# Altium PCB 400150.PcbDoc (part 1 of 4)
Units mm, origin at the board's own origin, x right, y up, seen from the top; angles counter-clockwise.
Board outline 101.6 x 63.5 mm, 4 copper layers (Top Layer, Mid-Layer 1, Mid-Layer 2, Bottom Layer), stack 1.582 mm thick; 248 components, 179 nets, 1093 pads, 875 vias.
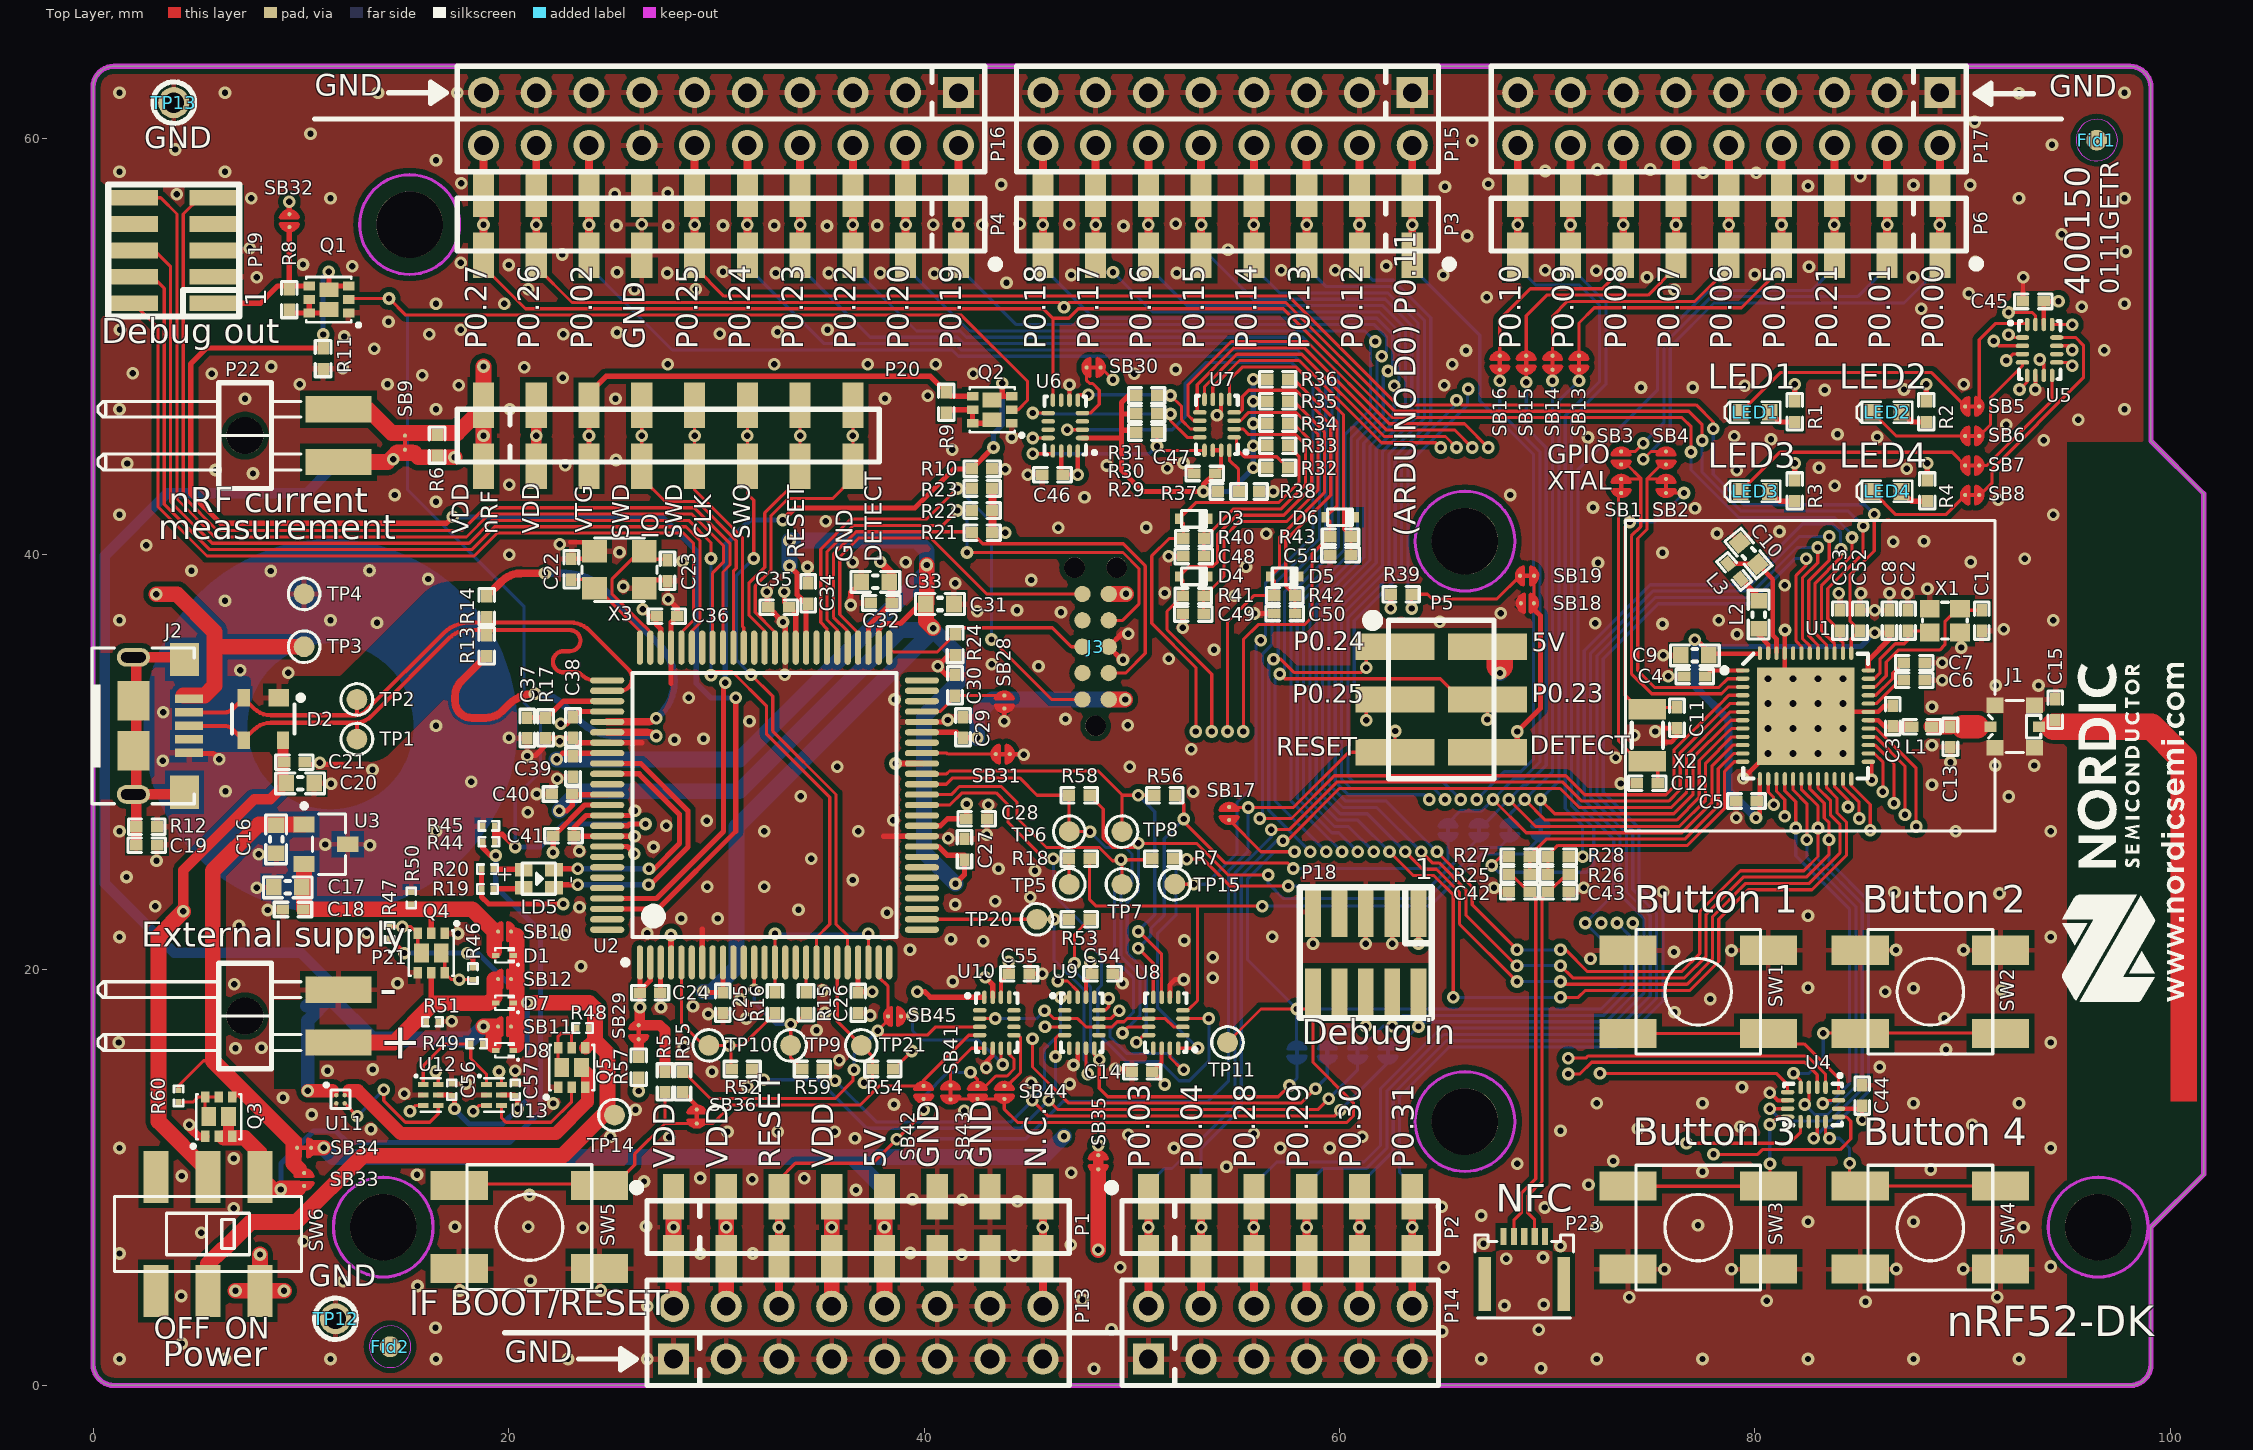
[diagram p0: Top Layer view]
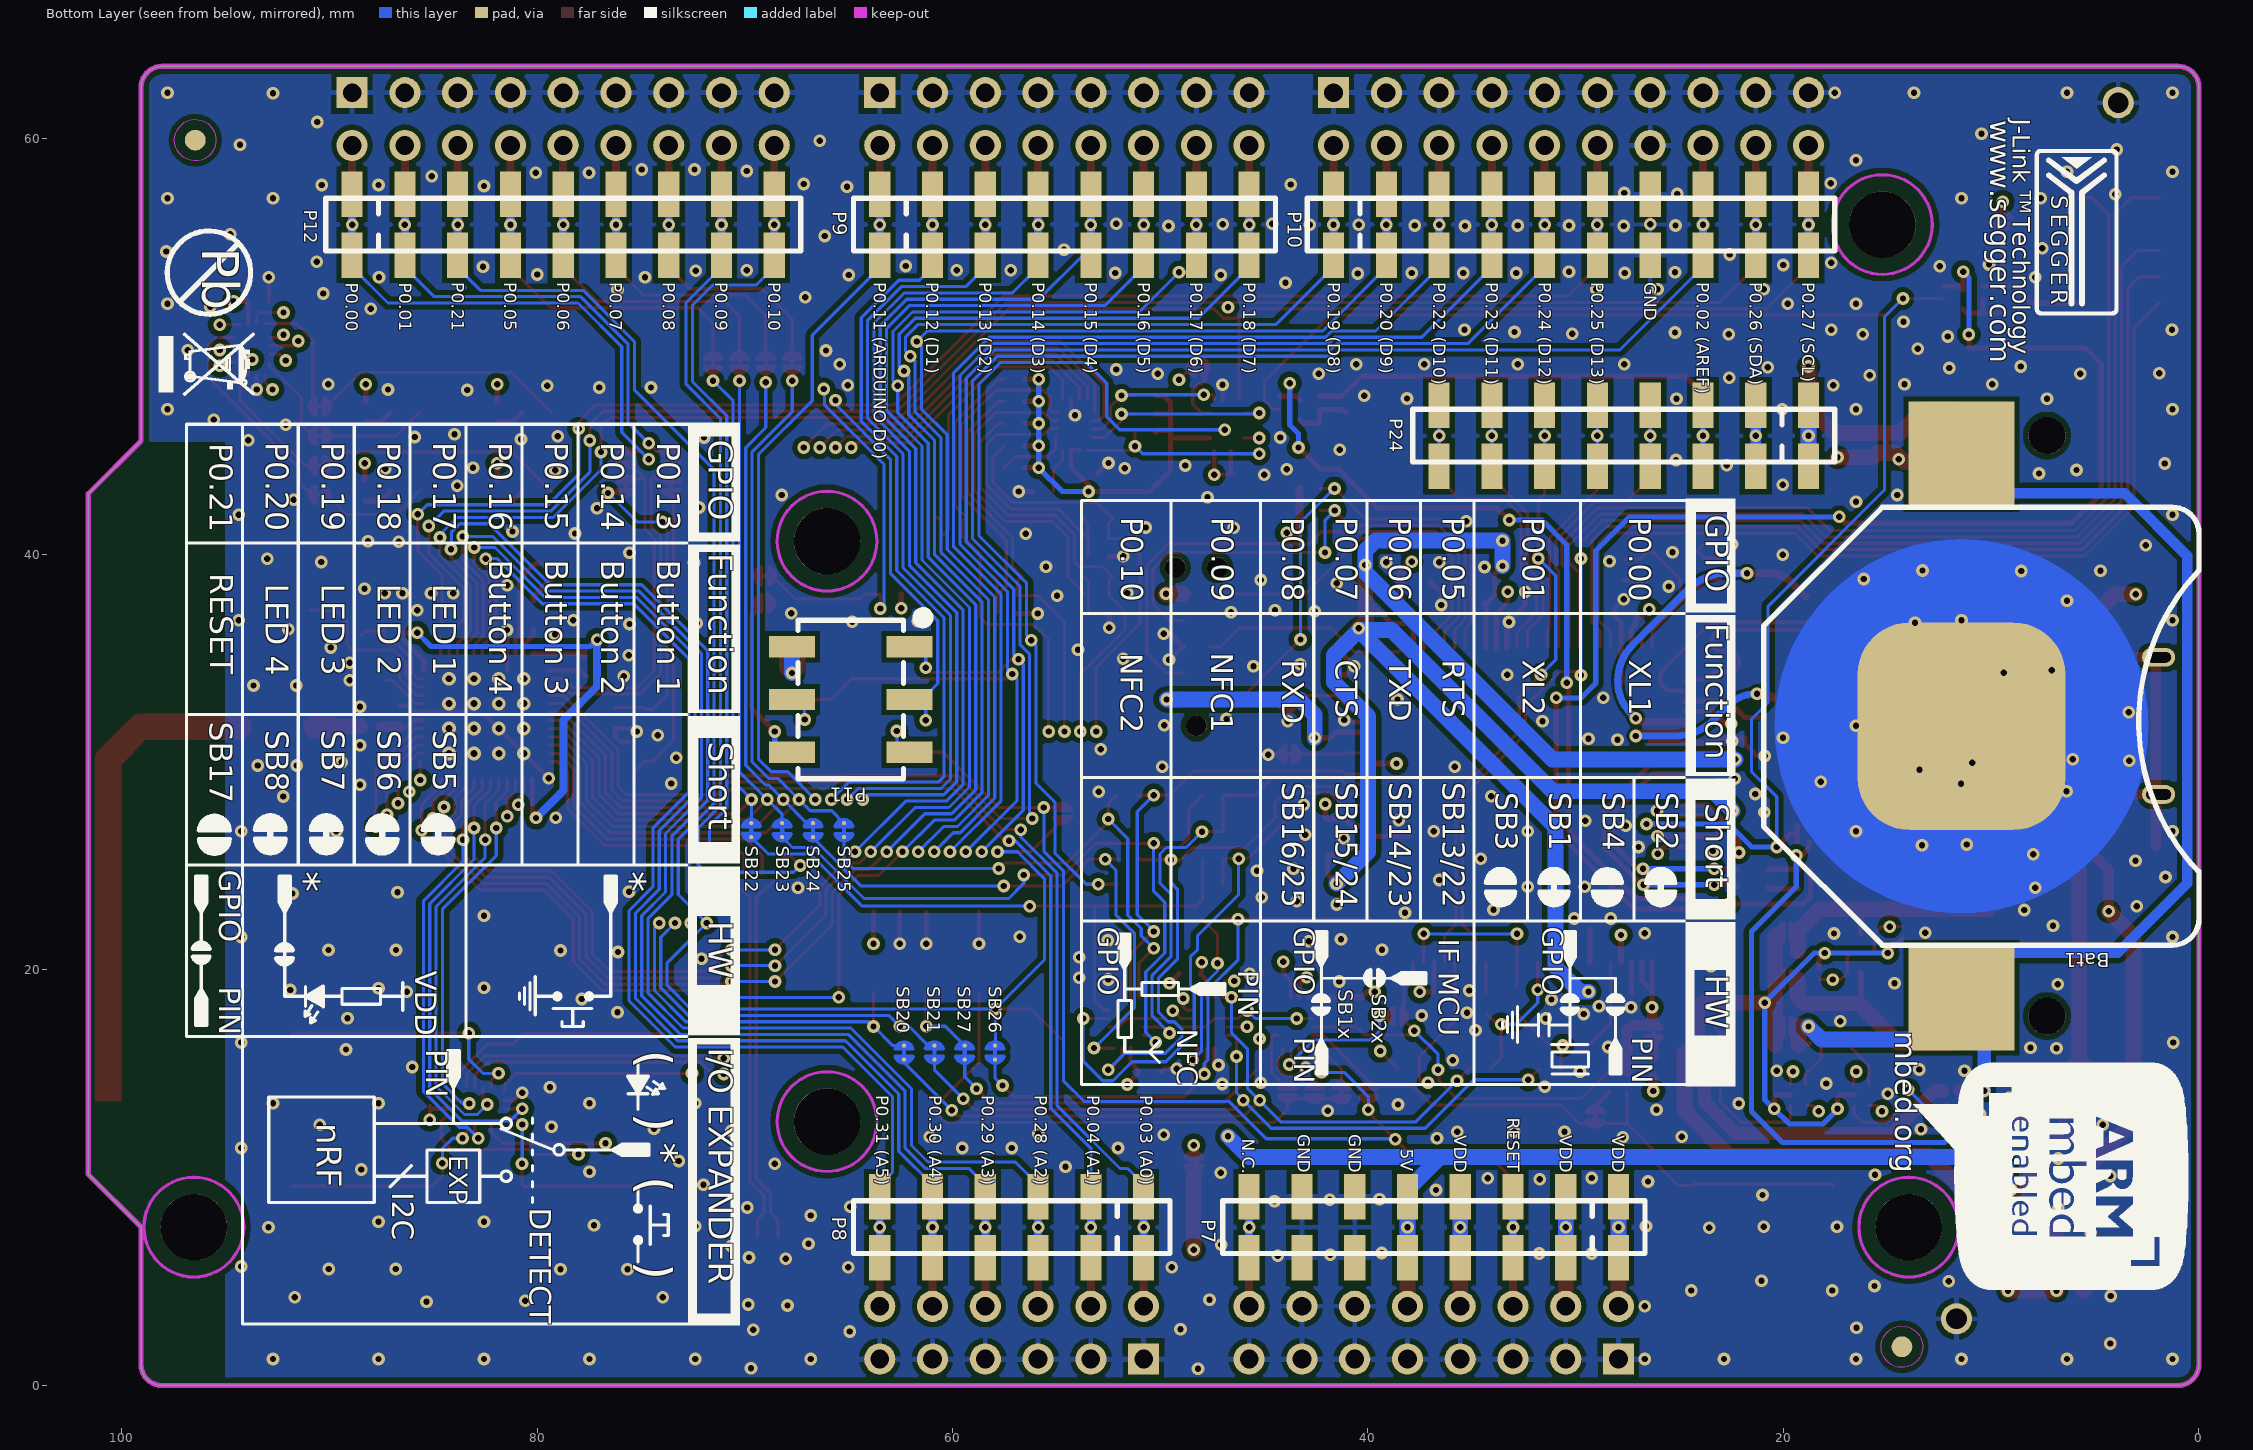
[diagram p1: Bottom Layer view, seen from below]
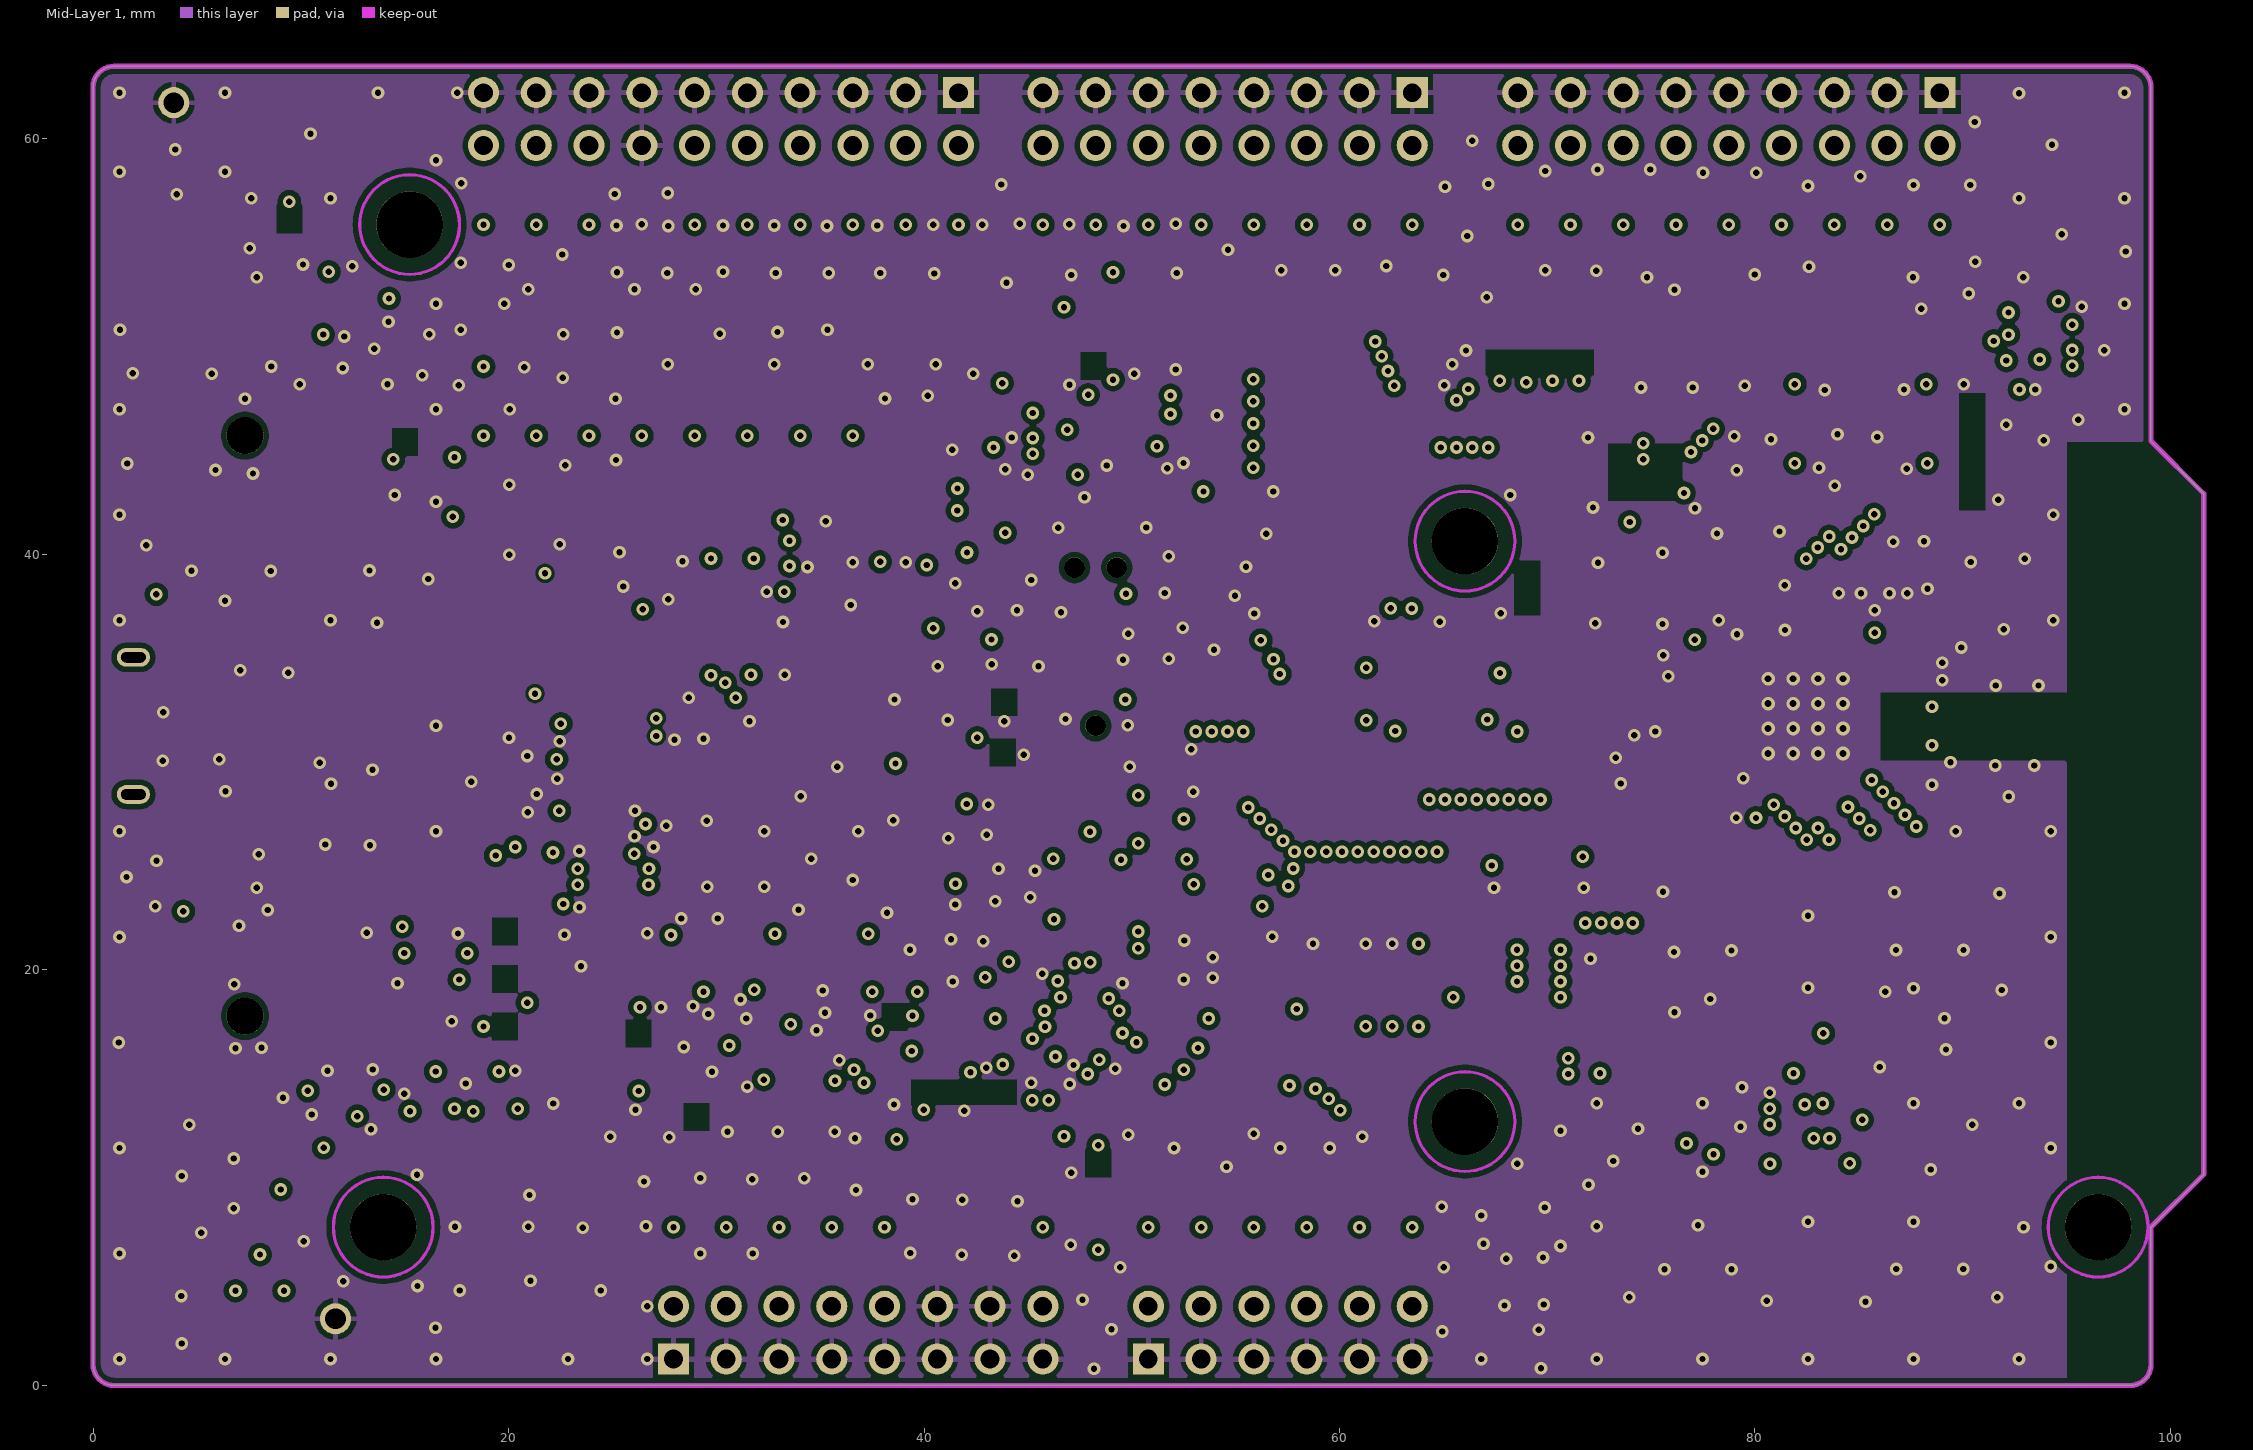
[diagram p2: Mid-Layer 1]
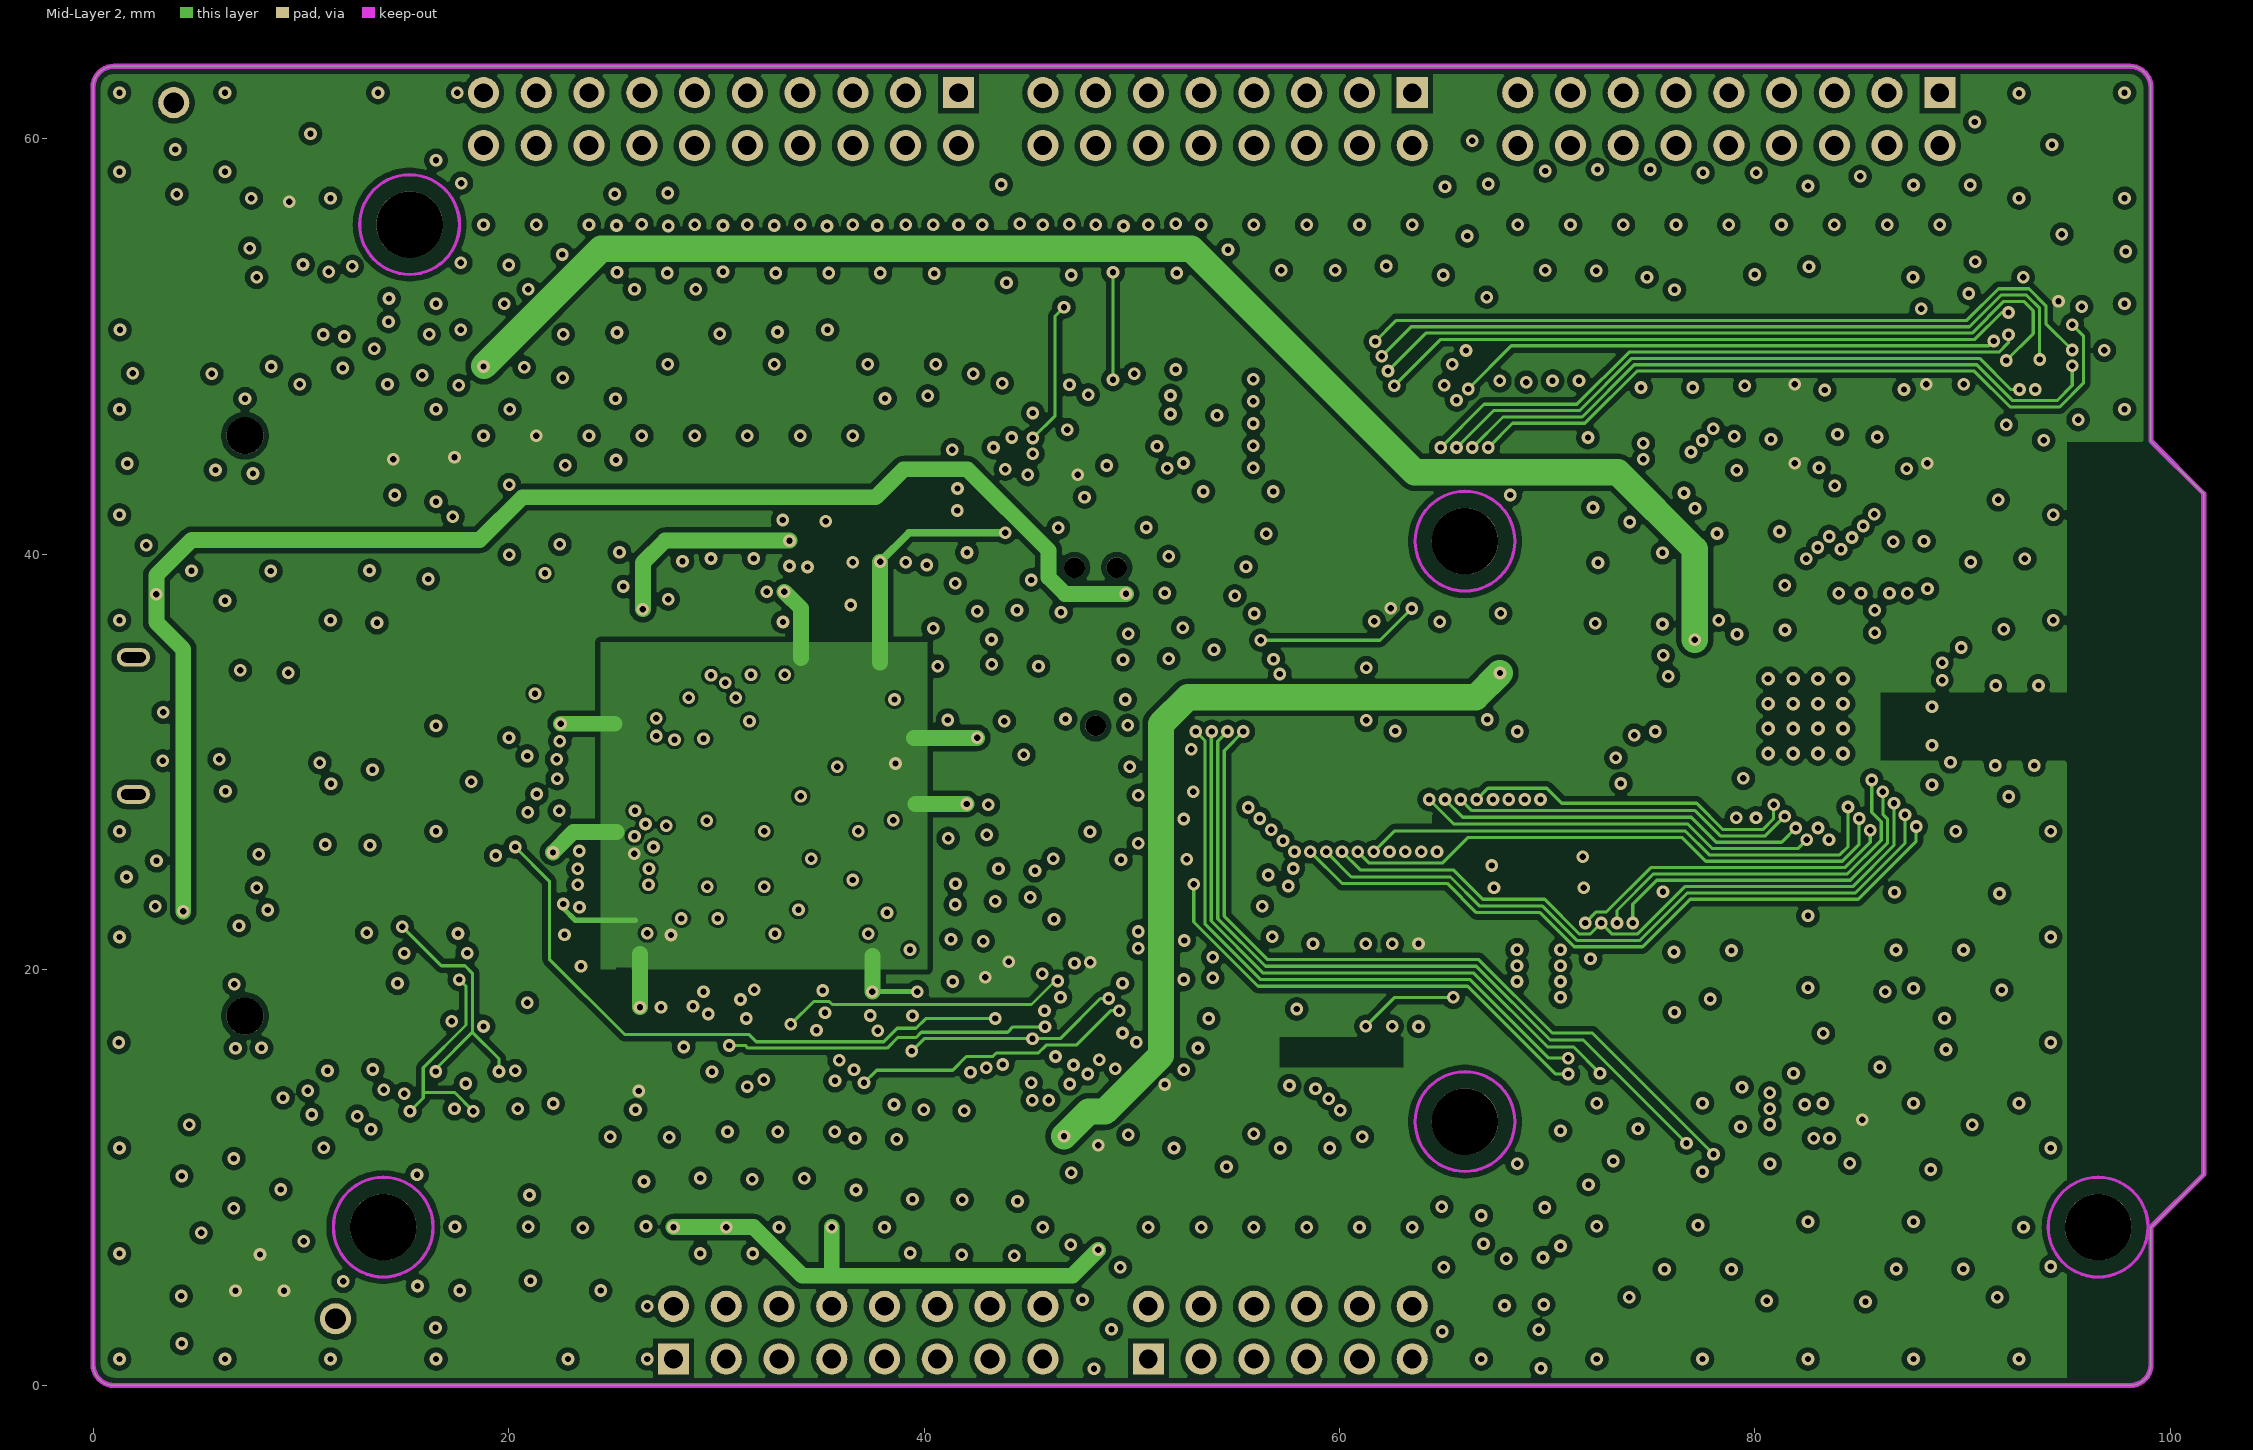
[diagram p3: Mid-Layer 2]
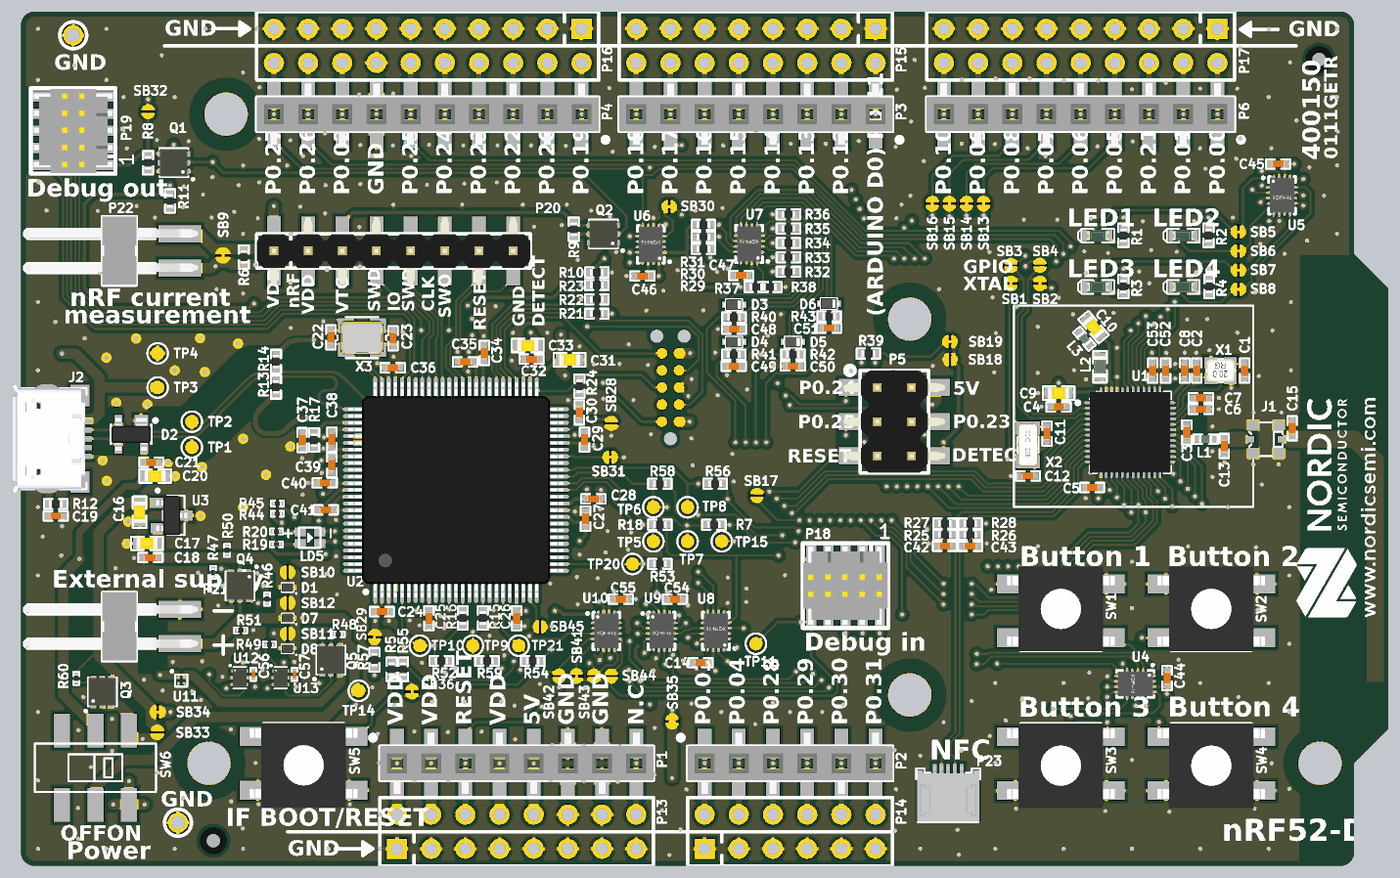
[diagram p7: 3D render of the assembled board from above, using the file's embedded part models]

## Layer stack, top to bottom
Top Solder: solder mask 0.0102, Solder Resist, Dk 3.5
Top Layer: signal copper 0.0356
Dielectric1: prepreg 0.18, FR-4, Dk 4.4
Mid-Layer 1: signal copper 0.0356
Dielectric2: core 1.08, FR-4, Dk 4.4
Mid-Layer 2: signal copper 0.0356
Dielectric3: prepreg 0.18, FR-4, Dk 4.4
Bottom Layer: signal copper 0.0356
Bottom Solder: solder mask 0.0102, Solder Resist, Dk 3.5

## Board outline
0,1.006 0,62.499 cw(c1.003,62.487) 1.016,63.49 98.044,63.49 cw(c98.044,62.474) 99.06,62.474 99.06,45.456 101.6,42.916 101.6,10.15 99.06,7.61 99.06,1.006 cw(c98.057,0.993) 98.069,-0.01 1.016,-0.01 cw(c1.016,1.006)

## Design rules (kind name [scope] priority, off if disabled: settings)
Clearance USB_Poly_Clearance [(InNamedPolygon('Top_Layer-GND')) vs (OnLayer('Mechanical 3'))] p1: gap=0.254 ignorepadtopadclearanceinfootprint=FALSE except(0: Arc-Hole Track-Hole SMDPad-Hole THPad-Hole Via-Hole Fill-Hole Poly-Hole Region-Hole Text-Hole)
Clearance USB_Clearance [(InDifferentialPairClass('All Differential Pairs'))] p2: gap=0.152 ignorepadtopadclearanceinfootprint=FALSE except(0: Arc-Hole Track-Hole SMDPad-Hole THPad-Hole Via-Hole Fill-Hole Poly-Hole Region-Hole Text-Hole)
Clearance ANT_Clerance [InNet('ANT') or InNet('RF')] p3: gap=0.203 ignorepadtopadclearanceinfootprint=FALSE except(0: Arc-Hole Track-Hole SMDPad-Hole THPad-Hole Via-Hole Fill-Hole Poly-Hole Region-Hole Text-Hole)
Clearance Polygon_Clearance [(InNamedPolygon('Top_Layer-GND')) or (InNamedPolygon('Bottom_Layer-GND')) or (InNamedPolygon('Mid_Layer_1-GND')) or (InNamedPolygon('Mid_Layer_2-VDD'))] p4: gap=0.254 ignorepadtopadclearanceinfootprint=FALSE except(0: Arc-Hole Track-Hole SMDPad-Hole THPad-Hole Via-Hole Fill-Hole Poly-Hole Region-Hole Text-Hole)
Clearance SB_Clearance [HasFootprint('Solderbridge') or HasFootprint('QFN40P180X140X55-10N')] p5: gap=0.127 ignorepadtopadclearanceinfootprint=FALSE except(0: Arc-Hole Track-Hole SMDPad-Hole THPad-Hole Via-Hole Fill-Hole Poly-Hole Region-Hole Text-Hole)
Clearance CSP_Clearance [HasFootprint('BGA4C40P2X2_76X76X62')] p6: gap=0.127 ignorepadtopadclearanceinfootprint=FALSE except(0: Arc-Hole Track-Hole SMDPad-Hole THPad-Hole Via-Hole Fill-Hole Poly-Hole Region-Hole Text-Hole)
Clearance P23_Clearance [HasFootprint('FPC_05P-0.5mm-RA-SMD')] p7: gap=0.127 ignorepadtopadclearanceinfootprint=FALSE except(0: Arc-Hole Track-Hole SMDPad-Hole THPad-Hole Via-Hole Fill-Hole Poly-Hole Region-Hole Text-Hole)
Clearance [All] p8: gap=0.152 ignorepadtopadclearanceinfootprint=FALSE except(0: Arc-Hole Track-Hole SMDPad-Hole THPad-Hole Via-Hole Fill-Hole Poly-Hole Region-Hole Text-Hole)
ComponentClearance [All] p1 off: gap=0.254 collisioncheckmode=3 verticalgap=0.254 showdistances=FALSE
DiffPairsRouting [All] p1: maxlimit=0.254 minlimit=0.15 mostfreqgap=0.254 toplayer_maxgap=0.15 toplayer_prefgap=0.15 toplayer_minwidth=0.203 toplayer_maxwidth=0.381 toplayer_prefwidth=0.381 midlayer1_mingap=0.254 midlayer1_minwidth=0.203 midlayer1_maxwidth=0.381 midlayer1_prefwidth=0.381 midlayer2_mingap=0.254 midlayer2_minwidth=0.203 midlayer2_maxwidth=0.381 midlayer2_prefwidth=0.381 bottomlayer_maxgap=0.15 bottomlayer_prefgap=0.15 bottomlayer_minwidth=0.203 bottomlayer_maxwidth=0.381 bottomlayer_prefwidth=0.381 maxuncoupledlength=12.7
FabricationTestPointUsage TestPointUsage [All] p1: valid=0 allowmultiple=FALSE
FabricationTestpoint Testpoint [All] p1: side=3 testpointundercomponent=TRUE minsize=1.016 maxsize=2.54 preferedsize=1.524 minholesize=0 maxholesize=1.016 preferedholesize=0.813 testpointgrid=0.025 allowsidetop=TRUE allowsidebottom=TRUE usegrid=TRUE gridtolerance=0
Height [All] p1 off: minheight=0 maxheight=25.4 prefheight=12.7
HoleSize [All] p1: absolutevalues=TRUE maxlimit=5 minlimit=0.305 maxpercent=80.000 minpercent=20.000
HoleToHoleClearance HoleToHoleClearance_L1L2 [InDrillLayerPair('Top Layer - Mid-Layer 1') vs InDrillLayerPair('Top Layer - Mid-Layer 1')] p1: gap=0.225 allowstackedmicrovias=TRUE
HoleToHoleClearance HoleToHoleClearance_L1L2_L1L3 [InDrillLayerPair('Top Layer - Mid-Layer 1') vs InDrillLayerPair('Top Layer - Mid-Layer 2')] p2: gap=0.225 allowstackedmicrovias=TRUE
HoleToHoleClearance HoleToHoleClearance_L1L3 [InDrillLayerPair('Top Layer - Mid-Layer 2') vs InDrillLayerPair('Top Layer - Mid-Layer 2')] p3: gap=0.225 allowstackedmicrovias=TRUE
HoleToHoleClearance HoleToHoleClearance_L1L3_L3L4 [InDrillLayerPair('Top Layer - Mid-Layer 2') vs InDrillLayerPair('Mid-Layer 2 - Mid-Layer 3')] p4: gap=0.225 allowstackedmicrovias=TRUE
HoleToHoleClearance HoleToHoleClearance_L3L4 [InDrillLayerPair('Mid-Layer 2 - Mid-Layer 3') vs InDrillLayerPair('Mid-Layer 2 - Mid-Layer 3')] p5: gap=0.225 allowstackedmicrovias=TRUE
HoleToHoleClearance HoleToHoleClearance_L3L4_L4L6 [InDrillLayerPair('Mid-Layer 2 - Mid-Layer 3') vs InDrillLayerPair('Mid-Layer 3 - Bottom Layer')] p6: gap=0.225 allowstackedmicrovias=TRUE
HoleToHoleClearance HoleToHoleClearance_L4L6 [InDrillLayerPair('Mid-Layer 3 - Bottom Layer') vs InDrillLayerPair('Mid-Layer 3 - Bottom Layer')] p7: gap=0.225 allowstackedmicrovias=TRUE
HoleToHoleClearance HoleToHoleClearance_L1L2_L1L6 [InDrillLayerPair('Top Layer - Mid-Layer 1') vs InDrillLayerPair('Top Layer - Bottom Layer')] p8: gap=0.275 allowstackedmicrovias=FALSE
HoleToHoleClearance HoleToHoleClearance_L1L3_L1L6 [InDrillLayerPair('Top Layer - Mid-Layer 2') vs InDrillLayerPair('Top Layer - Bottom Layer')] p9: gap=0.275 allowstackedmicrovias=FALSE
HoleToHoleClearance HoleToHoleClearance_L3L4_L1L6 [InDrillLayerPair('Mid-Layer 2 - Mid-Layer 3') vs InDrillLayerPair('Top Layer - Bottom Layer')] p10: gap=0.275 allowstackedmicrovias=FALSE
HoleToHoleClearance HoleToHoleClearance_L4L6_L1L6 [InDrillLayerPair('Mid-Layer 3 - Bottom Layer') vs InDrillLayerPair('Top Layer - Bottom Layer')] p11: gap=0.275 allowstackedmicrovias=FALSE
HoleToHoleClearance HoleToHoleClearance_L1L6 [InDrillLayerPair('Top Layer - Bottom Layer') vs InDrillLayerPair('Top Layer - Bottom Layer')] p12: gap=0.45 allowstackedmicrovias=FALSE
HoleToHoleClearance [All] p13: gap=0.254 allowstackedmicrovias=TRUE
MinimumAnnularRing [All] p1 off: minimumring=0.152
MinimumSolderMaskSliver MinimumSolderMaskSliver_U11 [InComponent('U11')] p1: minsoldermaskwidth=0.08
MinimumSolderMaskSliver [All] p2: minsoldermaskwidth=0.097
PolygonConnect PolygonConnect_1 [isVia and innet(gnd) or isVia and innet('VDD') or HasFootprint('COAXIAL-SWF') or isVia and innet('VDD_SAM')] p1: connectstyle=Direct reliefconductorwidth=0.254 reliefentries=4 polygonreliefangle="90 Angle" airgapwidth=0.254
PolygonConnect [All] p2: connectstyle=Relief reliefconductorwidth=0.254 reliefentries=4 polygonreliefangle="90 Angle" airgapwidth=0.254
RoutingVias [All] p1: holewidth=0.305 width=0.61 viastyle="Through Hole" minholewidth=0.305 minwidth=0.61 maxholewidth=0.711 maxwidth=1.27
SilkToSolderMaskClearance SilkscreenOverComponentPads [IsPad] p1: minsilkscreentomaskgap=0.254 clearancetoexposedcopper=TRUE
SolderMaskExpansion [All] p1: expansion=0.076
Width [All] p1: maxlimit=10.16 minlimit=0.152 preferedwidth=0.152 minimp=50.000000 maximp=50.000000 favimp=50.000000
21 further rules are at their usual default settings.

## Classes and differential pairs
component class sheet1_cover: Fid1 Fid2
component class sheet2_radio: C1 C2 C3 C4 C5 C6 C7 C8 C9 C10 C11 C12 C13 C15 C52 C53 J1 L1 L2 L3 SB1 SB2 SB3 SB4 U1 X1 X2
component class sheet3_pin_map: SB13 SB14 SB15 SB16 SB17 SB30 TP11
component class sheet4_interface_mcu: C14 C22 C23 C24 C25 C26 C27 C28 C29 C30 C31 C32 C33 C34 C35 C36 C37 C38 C39 C40 C41 C54 C55 LD5 Q1 Q2 R7 R8 R9 R10 R11 R15 R16 R17 R18 R19 R20 R52 R53 R54 R55 R56 R57 R58 R59 SB20 SB21 SB22 SB23 SB24 SB25 SB26 SB27 SB28 SB29 SB31 SB36 SB41 SB42 SB43 SB44 SB45 SB? TP5 TP6 TP7 TP8 TP9 TP10 TP20 TP21 U2 U8 U9 U10 X3
component class sheet5_buttons_and_leds: C44 C45 C46 C47 C48 C49 C50 C51 D3 D4 D5 D6 LED1 LED2 LED3 LED4 R1 R2 R3 R4 R5 R29 R30 R31 R32 R33 R34 R35 R36 R37 R38 R40 R41 R42 R43 SB5 SB6 SB7 SB8 SW1 SW2 SW3 SW4 SW5 U4 U5 U6 U7
component class sheet6_connectors: C19 C20 C21 C42 C43 D2 J2 J3 P1 P2 P3 P4 P5 P6 P7 P8 P9 P10 P11 P12 P13 P14 P15 P16 P17 P18 P19 P20 P23 P24 R12 R13 R14 R21 R22 R23 R24 R25 R26 R27 R28 R39 SB18 SB19 SB32 TP1 TP2 TP3 TP4 TP15
component class sheet7_power_supply: Bat1 C16 C17 C18 C56 C57 D1 D7 D8 P21 P22 Q3 Q4 Q5 R6 R44 R45 R46 R47 R48 R49 R50 R51 R60 SB9 SB10 SB11 SB12 SB33 SB34 SB35 SW6 TP12 TP13 TP14 U3 U11 U12 U13
differential pair DHSD: +DHSD_P -DHSD_N
differential pair DFSD: +DFSD_P -DFSD_N

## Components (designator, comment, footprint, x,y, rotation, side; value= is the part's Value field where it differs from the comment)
Bat1 "Bat Holder CR2032" CR2032_HOLDER_SMD 11.43,31.725 r270 bottom locked
C1 "12pF" CAPC1005X04L 90.918,36.809 r270 top
C2 "12pF" CAPC1005X04L 87.362,36.809 r90 top
C3 "0.8pF" CAPC1005X04L 86.626,32.211 r270 top
C4 "100nF" CAPC1005X04L 77.101,34.116 r180 top
C5 "100nF" CAPC1005X04L 79.59,28.122 r180 top
C6 "N.C." CAPC1005X04L 87.667,33.938 r0 top
C7 "100pF" CAPC1005X04L 87.667,34.777 r0 top
C8 "100nF" CAPC1005X04L 86.473,36.809 r90 top
C9 "4.7µF" CAPC1608X06L 77.101,35.132 r180 top
C10 "1.0µF" CAPC1608X06L 79.692,40.04 r310 top
C11 "12pF" CAPC1005X04L 76.241,32.127 r90 top
C12 "12pF" CAPC1005X04L 74.819,28.977 r0 top
C13 "N.C." CAPC1005X04L 89.408,31.206 r270 top
C14 "100nF" CAPC1005X04L 50.495,15.088 r0 top
C15 "1.2pF" CAPC1005X04L 94.459,32.516 r90 top
C16 "1.0µF" CAPC1608X06L 8.814,26.279 r90 top
C17 "1.0µF" CAPC1608X06L 9.373,23.967 r0 top
C18 "100nF" CAPC1005X04L 9.627,22.901 r0 top
C19 "100nF" CAPC1005X04L 2.587,25.999 r180 top
C20 "10µF" CAPC1608X06L 9.972,28.971 r180 top
C21 "100nF" CAPC1005X04L 9.693,29.987 r180 top
C22 "18pF" CAPC1005X04L 23.028,39.284 r90 top
C23 "18pF" CAPC1005X04L 27.651,39.207 r270 top
C24 "100nF" CAPC1005X04L 26.812,18.887 r180 top
C25 "100nF" CAPC1005X04L 30.318,18.405 r90 top
C26 "100nF" CAPC1005X04L 36.83,18.405 r90 top
C27 "100nF" CAPC1005X04L 41.951,25.796 r270 top
C28 "100nF" CAPC1005X04L 42.535,27.269 r180 top
C29 "100nF" CAPC1005X04L 41.875,31.664 r270 top
C30 "10nF" CAPC1005X04L 41.494,33.696 r270 top
C31 "10µF" CAPC1608X06L 40.767,37.607 r180 top
C32 "100nF" CAPC1005X04L 37.938,37.658 r0 top
C33 "10µF" CAPC1608X06L 37.658,38.674 r0 top
C34 "100nF" CAPC1005X04L 34.432,38.115 r270 top
C35 "100nF" CAPC1005X04L 33.01,37.455 r0 top
C36 "100nF" CAPC1005X04L 27.625,37.023 r0 top
C37 "10pF" CAPC1005X04L 20.894,31.638 r90 top
C38 "100nF" CAPC1005X04L 23.104,31.664 r90 top
C39 "100nF" CAPC1005X04L 23.104,29.784 r90 top
C40 "100nF" CAPC1005X04L 22.571,28.463 r0 top
C41 "100nF" CAPC1005X04L 22.647,26.457 r180 top
C42 "300pF" CAPC1005X04L 68.656,23.749 r180 top
C43 "300pF" CAPC1005X04L 70.536,23.749 r180 top
C44 "100nF" CAPC1005X04L 85.158,13.945 r270 top
C45 "100nF" CAPC1005X04L 93.396,52.172 r0 top
C46 "100nF" CAPC1005X04L 46.185,43.835 r0 top
C47 "100nF" CAPC1005X04L 53.518,43.885 r0 top
C48 "1.0µF" CAPC1005X04L 52.984,39.898 r180 top
C49 "1.0µF" CAPC1005X04L 52.961,37.129 r0 top
C50 "1.0µF" CAPC1005X04L 57.361,37.147 r0 top
C51 "1.0µF" CAPC1005X04L 60.048,39.972 r180 top
C52 "12pF" CAPC1005X04L 85.051,36.809 r90 top
C53 "12pF" CAPC1005X04L 84.086,36.809 r90 top
C54 "100nF" CAPC1005X04L 48.59,19.812 r180 top
C55 "100nF" CAPC1005X04L 44.577,19.812 r180 top
C56 "100nF" CAPC0603X03L_C 17.272,14.224 r270 top
C57 "100nF" CAPC0603X03L_C 20.32,14.224 r270 top
D1 "NSR0620P2T5G" SODFL100X40-2N 19.812,20.691 r180 top
D2 "PRTR5V0U2X" SOT190P230X110-4L 8.194,32.07 r270 top
D3 "1PS79SB30.115" SOD-523 52.99,41.701 r180 top
D4 "1PS79SB30.115" SOD-523 52.992,38.932 r180 top
D5 "1PS79SB30.115" SOD-523 57.361,38.932 r180 top
D6 "1PS79SB30.115" SOD-523 60.028,41.783 r180 top
D7 "NSR0620P2T5G" SODFL100X40-2N 19.812,18.405 r180 top
D8 "NSR0620P2T5G" SODFL100X40-2N 19.812,16.119 r180 top
Fid1 "Fiducial mark" Fiducial 96.451,59.934 r180 top
Fid2 "Fiducial mark" Fiducial 14.3,1.854 r0 top
J1 "MM8130-2600" COAXIAL-SWF 92.504,31.703 r90 top
J2 "MicroUSB-B" USB-Micro-B-RA-SMD-PiP 4.619,31.74 r0 top
J3 "TC2050-IDC" TC2050-IDC-NLFP 48.26,35.55 r90 top locked
L1 "3.9nH" INDC1005X04L 88.023,31.703 r0 top
L2 "10µH" INDC1608X06L 80.174,37.093 r270 top
L3 "15nH" INDC1005X04L 79.007,39.176 r310 top
LD5 "LED RG" LED_DUAL_0606 21.463,24.384 r90 top
LED1 "L0603G" LED_0603_G 80.01,46.837 r0 top
LED2 "L0603G" LED_0603_G 86.36,46.837 r0 top
LED3 "L0603G" LED_0603_G 80.01,43.027 r0 top
LED4 "L0603G" LED_0603_G 86.36,43.027 r0 top
P1 "Socket 1x8" SOCKET_1x8_SMD 27.94,7.61 r0 top locked
P2 "Socket 1x6" SOCKET_1x6_SMD 50.8,7.61 r0 top locked
P3 "Socket 1x8" SOCKET_1x8_SMD 63.5,55.87 r180 top locked
P4 "Socket 1x10" SOCKET_1x10_SMD 41.656,55.87 r180 top locked
P5 "Pin Hdr 2x3" HDR_2x3-SMD 64.897,33.01 r270 top locked
P6 "Socket 1x9" SOCKET_1x9_SMD 88.9,55.87 r180 top locked
P7 "Pin List 1x8" LIST_1x8_SMD-NC 27.94,7.61 r0 bottom
P8 "Pin List 1x6" LIST_1x6_SMD-NC 50.8,7.61 r0 bottom locked
P9 "Pin List 1x8" LIST_1x8_SMD-NC 63.5,55.87 r180 bottom locked
P10 "Pin List 1x10" LIST_1x10_SMD-NC 41.656,55.87 r180 bottom locked
P11 "Socket 2x3" SOCKET_2x3_SMD-2.54mm-bottom-NC 64.897,33.01 r270 top locked
P12 "Pin List 1x9" LIST_1x9_SMD-NC 88.9,55.87 r180 bottom locked
P13 "Pin Header 2x8" HDR_2x8-NC 36.83,2.53 r0 top locked
P14 "Pin Header 2x6" HDR_2x6-NC 57.15,2.53 r0 top locked
P15 "Pin Header 2x8" HDR_2x8-NC 54.61,60.95 r180 top locked
P16 "Pin Header 2x10" HDR_2x10-NC 30.226,60.95 r180 top locked
P17 "Pin Header 2x9" HDR_2x9-NC 78.74,60.95 r180 top
P18 "Pin Header 2x5, 1.27mm" HDR_2x5-SMD-1.27mm-K 61.265,20.822 r180 top
P19 "Pin Header 2x5, 1.27mm" HDR_2x5-SMD-1.27mm-K 3.886,54.625 r90 top locked
P20 "Pin List 1x8" LIST_1x8_SMD 18.796,45.71 r0 top
P21 "Pin List 1x2, Angled" LIST_ANG_1x2-SMD-2.54MM 11.811,17.77 r270 top
P22 "Pin List 1x2, Angled" LIST_ANG_1x2-SMD-2.54MM 11.811,45.71 r270 top
P23 "FPC 0.5mm RA SMD" FPC_05P-0.5mm-RA-SMD 67.894,7.163 r0 top
P24 "Socket 1x8" LIST_1x8_SMD-NC 18.796,45.71 r0 bottom
Q1 "TSM2537CQ RFG" DFN65P200X200X80_HS-6N 11.354,52.263 r180 top
Q2 "TSM2537CQ RFG" DFN65P200X200X80_HS-6N 43.282,46.954 r180 top
Q3 "TSM2537CQ RFG" DFN65P200X200X80_HS-6N 6.045,12.929 r90 top
Q4 "TSM250N02DCQ RFG" DFN65P200X200X80_HS-6N 16.281,20.803 r270 top
Q5 "TSM2537CQ RFG" DFN65P200X200X80_HS-6N 23.038,15.291 r90 top
R1 "220R" RESC1005X04L 81.915,46.863 r90 top
R2 "220R" RESC1005X04L 88.24,46.863 r90 top
R3 "220R" RESC1005X04L 81.915,43.053 r90 top
R4 "220R" RESC1005X04L 88.291,43.053 r90 top
R5 "10k" RESC1005X04L 27.532,14.601 r90 top
R6 "N.C." RESC1005X04L 16.561,45.253 r90 top
R7 "0R" RESC1005X04L 51.486,25.349 r180 top
R8 "10k" RESC1005X04L 9.449,52.263 r270 top
R9 "10k" RESC1005X04L 41.072,47.31 r270 top
R10 "10k" RESC1005X04L 42.795,44.11 r180 top
R11 "10k" RESC1005X04L 11.074,49.418 r90 top
R12 "10k" RESC1005X04L 2.587,26.888 r180 top
R13 "39R" RESC1005X04L 18.949,35.593 r90 top
R14 "39R" RESC1005X04L 18.949,37.479 r270 top
R15 "150R" RESC1005X04L 34.324,18.415 r270 top
R16 "150R" RESC1005X04L 32.826,18.415 r270 top
R17 "6k8" RESC1005X04L 21.783,31.638 r90 top
R18 "0R" RESC1005X04L 47.473,25.349 r180 top
R19 "220R" RESC0603X03L_C 18.989,23.893 r180 top
R20 "220R" RESC0603X03L_C 18.989,24.844 r180 top
R21 "4k7" RESC1005X04L 42.795,41.036 r0 top
R22 "4k7" RESC1005X04L 42.795,42.103 r0 top
R23 "4k7" RESC1005X04L 42.795,43.17 r0 top
R24 "4k7" RESC1005X04L 41.494,35.651 r270 top
R25 "0R" RESC1005X04L 68.652,24.602 r0 top
R26 "0R" RESC1005X04L 70.532,24.602 r180 top
R27 "N.C." RESC1005X04L 68.652,25.441 r0 top
R28 "N.C." RESC1005X04L 70.532,25.441 r180 top
R29 "4k7" RESC1005X04L 50.714,45.867 r180 top
R30 "4k7" RESC1005X04L 50.714,46.756 r180 top
R31 "12k" RESC1005X04L 50.714,47.645 r180 top
R32 "12k" RESC1005X04L 57.021,44.161 r180 top
R33 "100k" RESC1005X04L 57.021,45.228 r180 top
R34 "100k" RESC1005X04L 57.021,46.295 r180 top
R35 "100k" RESC1005X04L 57.021,47.361 r180 top
R36 "100k" RESC1005X04L 57.021,48.428 r180 top
R37 "N.C." RESC1005X04L 54.643,43.022 r180 top
R38 "0R" RESC1005X04L 55.643,43.022 r180 top
R39 "1M0" RESC1005X04L 62.967,38.075 r180 top
R40 "18k" RESC1005X04L 52.984,40.761 r180 top
R41 "18k" RESC1005X04L 52.961,37.993 r180 top
R42 "18k" RESC1005X04L 57.361,38.01 r180 top
R43 "18k" RESC1005X04L 60.048,40.835 r180 top
R44 "33k" RESC0603X03L_C 19.05,26.162 r0 top
R45 "47k" RESC0603X03L_C 19.05,26.924 r180 top
R46 "1M0" RESC0603X03L_C 18.288,19.812 r270 top
R47 "1M0" RESC0603X03L_C 14.275,21.793 r90 top
R48 "1M0" RESC0603X03L_C 23.571,17.196 r180 top
R49 "100k" RESC0603X03L_C 18.466,16.434 r180 top
R50 "220k" RESC0603X03L_C 15.316,23.444 r90 top
R51 "220k" RESC0603X03L_C 16.332,17.501 r0 top
R52 "0R" RESC1005X04L 31.242,15.223 r180 top
R53 "0R" RESC1005X04L 47.473,22.428 r180 top
R54 "0R" RESC1005X04L 38.024,15.223 r180 top
R55 "0R" RESC1005X04L 28.396,14.601 r90 top
R56 "0R" RESC1005X04L 51.587,28.397 r180 top
R57 "0R" RESC1005X04L 26.266,15.306 r270 top
R58 "0R" RESC1005X04L 47.473,28.397 r180 top
R59 "0R" RESC1005X04L 34.629,15.223 r180 top
R60 "1M0" RESC0603X03L_C 4.115,13.919 r270 top
SB1 "Solderbridge" Solderbridge_Shorted 73.558,43.289 r90 top net-tie
SB2 "Solderbridge" Solderbridge_Shorted 75.717,43.289 r90 top net-tie
SB3 "Solderbridge" Solderbridge#1 73.558,44.635 r90 top
SB4 "Solderbridge" Solderbridge#1 75.717,44.635 r90 top
SB5 "Solderbridge" Solderbridge_Shorted 90.454,47.117 r180 top net-tie
SB6 "Solderbridge" Solderbridge_Shorted 90.454,45.695 r180 top net-tie
SB7 "Solderbridge" Solderbridge_Shorted 90.454,44.272 r180 top net-tie
SB8 "Solderbridge" Solderbridge_Shorted 90.454,42.85 r180 top net-tie
SB9 "Solderbridge" Solderbridge_Shorted 15.011,45.372 r270 top net-tie
SB10 "Solderbridge" Solderbridge#2 19.812,21.834 r180 top
SB11 "Solderbridge" Solderbridge#2 19.812,17.262 r180 top
SB12 "Solderbridge" Solderbridge#3 19.812,19.548 r180 top
SB13 "Solderbridge" Solderbridge_Shorted 71.526,49.218 r270 top net-tie
SB14 "Solderbridge" Solderbridge_Shorted 70.256,49.218 r270 top net-tie
SB15 "Solderbridge" Solderbridge_Shorted 68.986,49.218 r270 top net-tie
SB16 "Solderbridge" Solderbridge_Shorted 67.716,49.218 r270 top net-tie
SB17 "Solderbridge" Solderbridge#4 54.686,27.526 r270 top
SB18 "Solderbridge" Solderbridge#1 69.045,37.643 r0 top
SB19 "Solderbridge" Solderbridge_Shorted 69.03,38.964 r180 top net-tie
SB20 "Solderbridge" Solderbridge_Shorted 62.331,16.012 r90 bottom net-tie
SB21 "Solderbridge" Solderbridge_Shorted 60.872,16.012 r90 bottom net-tie
SB22 "Solderbridge" Solderbridge_Shorted 69.685,26.72 r90 bottom net-tie
SB23 "Solderbridge" Solderbridge_Shorted 68.199,26.72 r90 bottom net-tie
SB24 "Solderbridge" Solderbridge_Shorted 66.713,26.72 r90 bottom net-tie
SB25 "Solderbridge" Solderbridge_Shorted 65.227,26.72 r90 bottom net-tie
SB26 "Solderbridge" Solderbridge_Shorted 57.953,16.012 r90 bottom net-tie
SB27 "Solderbridge" Solderbridge_Shorted 59.412,16.012 r90 bottom net-tie
SB28 "Solderbridge" Solderbridge#1 43.866,32.888 r270 top
SB29 "Solderbridge" Solderbridge_Shorted 26.266,16.993 r90 top net-tie
SB30 "Solderbridge" Solderbridge_Shorted 48.164,48.991 r180 top net-tie
SB31 "Solderbridge" Solderbridge_Shorted 43.79,30.378 r0 top net-tie
SB32 "Solderbridge" Solderbridge#1 9.449,56.058 r270 top
SB33 "Solderbridge" Solderbridge#1 10.16,9.906 r270 top
SB34 "Solderbridge" Solderbridge_Shorted 10.16,11.43 r180 top net-tie
SB35 "Solderbridge" Solderbridge_Shorted_Power 48.387,10.734 r90 top net-tie
SB36 "Solderbridge" Solderbridge_Shorted 29.063,12.935 r270 top net-tie
SB41 "Solderbridge" Solderbridge_Shorted 41.275,14.097 r270 top net-tie
SB42 "Solderbridge" Solderbridge#5 39.98,14.097 r270 top
SB43 "Solderbridge" Solderbridge#6 42.57,14.097 r270 top
SB44 "Solderbridge" Solderbridge#3 43.866,14.097 r270 top
SB45 "Solderbridge" Solderbridge#1 38.583,17.755 r180 top
SW1 "PB SW" Switch-PB-6.2x6.3mm-SMD 77.267,18.94 r0 top
SW2 "PB SW" Switch-PB-6.2x6.3mm-SMD 88.443,18.94 r0 top
SW3 "PB SW" Switch-PB-6.2x6.3mm-SMD 77.267,7.586 r180 top
SW4 "PB SW" Switch-PB-6.2x6.3mm-SMD 88.443,7.586 r180 top
SW5 "PB SW" Switch-PB-6.2x6.3mm-SMD 21.006,7.61 r180 top
SW6 "Switch" Switch-Slide-DPDT-8.5x3.6mm 5.537,7.28 r0 top locked
TP1 "Ø1.0mm,SMD" TP_SMD_Ø1.0mm 12.7,31.105 r0 top
TP2 "Ø1.0mm,SMD" TP_SMD_Ø1.0mm 12.7,33.01 r0 top
TP3 "Ø1.0mm,SMD" TP_SMD_Ø1.0mm 10.16,35.55 r0 top
TP4 "Ø1.0mm,SMD" TP_SMD_Ø1.0mm 10.16,38.09 r0 top
TP5 "Ø1.0mm,SMD" TP_SMD_Ø1.0mm 46.99,24.11 r0 top
TP6 "Ø1.0mm,SMD" TP_SMD_Ø1.0mm 46.99,26.65 r0 top
TP7 "Ø1.0mm,SMD" TP_SMD_Ø1.0mm 49.53,24.11 r0 top
TP8 "Ø1.0mm,SMD" TP_SMD_Ø1.0mm 49.53,26.65 r0 top
TP9 "Ø1.0mm,SMD" TP_SMD_Ø1.0mm 33.579,16.358 r0 top
TP10 "Ø1.0mm,SMD" TP_SMD_Ø1.0mm 29.642,16.358 r0 top
TP11 "Ø1.0mm,SMD" TP_SMD_Ø1.0mm 54.61,16.5 r90 top
TP12 "TP" TESTPAD-TH 11.672,3.198 r0 top
TP13 "TP" TESTPAD-TH 3.886,61.737 r0 top
TP14 "Ø1.0mm,SMD" TP_SMD_Ø1.0mm 25.102,13.002 r0 top
TP15 "Ø1.0mm,SMD" TP_SMD_Ø1.0mm 52.07,24.12 r90 top
TP20 "Ø1.0mm,SMD" TP_SMD_Ø1.0mm 45.441,22.428 r0 top
TP21 "Ø1.0mm,SMD" TP_SMD_Ø1.0mm 36.982,16.358 r0 top
U1 "nRF52832-QFAAE0" QFN40P600X600X90-48N 82.435,32.211 r0 top
U2 "ATSAM3U2CA-AU" TSQFP50P1600X1600X160-100N 32.324,27.93 r90 top locked
U3 "AP7333-33SAG-7" SOT-23A 10.16,26.99 r270 top
U4 "NX3DV2567" XQFN40P180X260X50-16N 82.795,13.513 r270 top
U5 "NX3DV2567" XQFN40P180X260X50-16N 93.701,49.835 r0 top
U6 "NX3DV2567" XQFN40P180X260X50-16N 46.803,46.197 r180 top
U7 "PCAL6408A" XQFN40P180X260X50-16N 54.1,46.228 r180 top
U8 "FSA2466UMX" XQFN40P180X260X50-16N 51.638,17.45 r180 top
U9 "FSA2466UMX" XQFN40P180X260X50-16N 47.596,17.45 r0 top
U10 "NX3DV2567" XQFN40P180X260X50-16N 43.504,17.45 r0 top
U11 "SC728CSTRT" BGA4C40P2X2_76X76X62 11.913,13.767 r0 top
U12 "NC7SV11L6X" DFN1410-6N 16.256,13.97 r0 top
U13 "NC7SV11L6X" DFN1410-6N 19.304,13.97 r0 top
X1 "32MHz" BT-XTAL_2016 89.14,36.809 r180 top
X2 "32.768kHz" XTAL_3215 74.819,31.289 r270 top
X3 "12MHz" BT-XTAL_3225 25.339,39.258 r180 top

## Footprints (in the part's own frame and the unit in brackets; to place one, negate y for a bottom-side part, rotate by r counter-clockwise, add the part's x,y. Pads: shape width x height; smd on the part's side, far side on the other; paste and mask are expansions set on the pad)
BGA4C40P2X2_76X76X62 [mm] "BGA, 4-Leads, Body 0.8x0.8mm,  Pitch 0.40mm"
  round 0.22 smd mask+0.05: A1(-0.2,0.2) A2(0.2,0.2) B1(-0.2,-0.2) B2(0.2,-0.2)
  silkscreen extent -0.74,-0.45 0.45,0.74, body extent -0.38,-0.38 0.38,0.38, height 0.63
BT-XTAL_2016 [mm] "Crystal 2.0 x 1.6 mm"
  rect 0.95x0.85 smd: 1(-0.725,-0.575) 2(0.725,-0.575) 3(0.725,0.575) 4(-0.725,0.575)
  silkscreen extent -1.08,-0.88 1.08,0.88, body extent -1.05,-0.85 1.05,0.85, height 0.56
BT-XTAL_3225 [mm] "Mercury X32 series"
  rect 1.2x1.1 smd: 1(-1.194,-0.89) 2(1.194,-0.89) 3(1.194,0.891) 4(-1.194,0.891)
  silkscreen extent -1.8,-1.52 1.8,1.52, body extent -1.6,-1.25 1.6,1.25, height 0.6
CAPC0603X03L_C [mm] "Chip Capacitor, 2-Leads, Body 0.6x0.3mm, IPC High Density"
  rect 0.27x0.3 smd: 1(-0.285,0) 2(0.285,0)
  silkscreen extent -0.49,-0.22 0.49,0.22, body extent -0.3,-0.15 0.31,0.15, height 0.3
CAPC1005X04L [mm] "Chip Capacitor, 2-Leads, Body 1.0x0.5mm, IPC High Density"
  rect 0.6x0.5 smd: 1(-0.5,0) 2(0.5,0)
  silkscreen extent -0.9,-0.35 0.9,0.35, body extent -0.51,-0.25 0.51,0.25, height 0.5
CAPC1608X06L [mm] "Chip Capacitor, 2-Leads, Body 1.6x0.8mm, IPC High Density"
  rect 0.75x0.8 smd: 1(-0.675,0) 2(0.675,0)
  silkscreen extent -1.17,-0.5 1.17,0.5, body extent -0.8,-0.43 0.8,0.43, height 0.8
COAXIAL-SWF [mm]
  rect 0.5x0.58 smd: 1(0,1.16) 3(0,-1.16)
  rect 0.75x0.8 smd: 2(-1.025,-0.95) 2(-1.025,0.95) 2(1.025,-0.95) 2(1.025,0.95)
  Top Layer pour cut-out: -0.65,0.55 0.65,0.55 0.65,1.35 -0.65,1.35
  Top Layer pour cut-out: 0.65,-0.55 -0.65,-0.55 -0.65,-1.35 0.65,-1.35
  silkscreen extent -1.25,-1.25 1.25,1.25, body extent -1.26,-1.3 1.26,1.3, height 1.55
CR2032_HOLDER_SMD [mm] "CR2032 - SMD mount coin cell bat holder"
  round 18 on Bottom Solder paste+0: 0(0,0)
  rect 5.08x5.08 smd: 1(-13.081,0) 1(13.081,0)
  rrect50% 10x10 smd paste-9: 2(0,0)
  Top Layer circle w5: c0,0 r6.5
  silkscreen extent -10.54,-9.53 10.54,11.43, body extent -15.37,-10.27 15.37,9.78, height 3.96
DFN65P200X200X80_HS-6N [mm] "DFN, 6-Leads, Body 2.00x2.00mm, Pitch 0.65mm, IPC Medium Density"
  rect 0.55x0.42 smd mask+0.055: 1(-0.945,0.65) 2(-0.945,0) 3(-0.945,-0.65) 4(0.945,-0.65) 5(0.945,0) 6(0.945,0.65)
  rect 0.92x0.71 smd mask+0.055: 3(0,-0.475) 6(0,0.475)
  silkscreen extent -1.48,-1.08 1.08,1.27, body extent -1.02,-1.02 1.02,1.02, height 0.8
DFN1410-6N [mm] "PSON, 6-Leads, Body 1,40x1,00mm, Pitch 0,50mm, IPC Medium Density"
  rect 0.525x0.25 smd mask+0.05: 1(-0.363,0.5) 2(-0.363,0) 3(-0.363,-0.5) 4(0.363,-0.5) 5(0.363,0) 6(0.363,0.5)
  silkscreen extent -0.76,-0.8 0.48,0.96, body extent -0.53,-0.72 0.53,0.72, height 0.4
Fiducial [mm] "Fiducial Mark"
  round 1 smd paste+0 mask+0.5: 0(0,0)
  round 1 smd far side paste+0 mask+0.5: 0(0,0)
  Top Layer keep-out circle w0.01: c0,0 r1
  Bottom Layer keep-out circle w0.01: c0,0 r1
FPC_05P-0.5mm-RA-SMD [mm] "FPC, 5-Leads, Pitch 0,5mm"
  rect 0.6x2.6 smd: 0(-0.9,-2.3) 0(2.9,-2.3)
  rect 0.3x0.8 smd mask+0.05: 1(0,0) 2(0.5,0) 3(1,0) 4(1.5,0) 5(2,0)
  silkscreen extent -1.38,-3.93 3.38,0.08, body extent -1.3,-3.85 3.3,0.2, height 1.2
HDR_2x3-SMD [mil] "Board-Board Conn, Header, 6-way, 2-row"
  rect 50x150 smd: 1(-100,-87.5) 2(-100,87.5) 3(0,-87.5) 4(0,87.5) 5(100,-87.5) 6(100,87.5)
  silkscreen extent -160,-140 150,100, body extent -150,-148 150,148, height 382
HDR_2x5-SMD-1.27mm-K [mm] "SMT MICRO HEADER, (1,27) .050\" Keying Shroud"
  rect 0.76x2.4 smd: 1(-2.54,-1.95) 2(-2.54,1.95) 3(-1.27,-1.95) 4(-1.27,1.95) 5(0,-1.95) 6(0,1.95) 7(1.27,-1.95) 8(1.27,1.95) 9(2.54,-1.95) 10(2.54,1.95)
  silkscreen extent -3.18,-3.15 3.18,3.15, body extent -3.14,-2.92 3.14,2.92, height 6.11
HDR_2x6-NC [mm] "Pin Header, 2.54mm through hole"
  rect 1.5x1.5 hole 0.9: 1(-6.35,-1.27)
  round 1.5 hole 0.9: 2(-6.35,1.27) 3(-3.81,-1.27) 4(-3.81,1.27) 5(-1.27,-1.27) 6(-1.27,1.27) 7(1.27,-1.27) 8(1.27,1.27) 9(3.81,-1.27) 10(3.81,1.27) 11(6.35,-1.27) 12(6.35,1.27)
  silkscreen extent -7.62,-2.54 7.62,2.54
HDR_2x8-NC [mm] "Pin Header, 2.54mm through hole"
  rect 1.5x1.5 hole 0.9: 1(-8.89,-1.27)
  round 1.5 hole 0.9: 2(-8.89,1.27) 3(-6.35,-1.27) 4(-6.35,1.27) 5(-3.81,-1.27) 6(-3.81,1.27) 7(-1.27,-1.27) 8(-1.27,1.27) 9(1.27,-1.27) 10(1.27,1.27) 11(3.81,-1.27) 12(3.81,1.27) 13(6.35,-1.27) 14(6.35,1.27) 15(8.89,-1.27) 16(8.89,1.27)
  silkscreen extent -10.16,-2.54 10.16,2.54
HDR_2x9-NC [mm] "Pin Header, 2.54mm through hole"
  rect 1.5x1.5 hole 0.9: 1(-10.16,-1.27)
  round 1.5 hole 0.9: 2(-10.16,1.27) 3(-7.62,-1.27) 4(-7.62,1.27) 5(-5.08,-1.27) 6(-5.08,1.27) 7(-2.54,-1.27) 8(-2.54,1.27) 9(0,-1.27) 10(0,1.27) 11(2.54,-1.27) 12(2.54,1.27) 13(5.08,-1.27) 14(5.08,1.27) 15(7.62,-1.27) 16(7.62,1.27) 17(10.16,-1.27) 18(10.16,1.27)
  silkscreen extent -11.43,-2.54 11.43,2.54
HDR_2x10-NC [mm] "Pin Header, 2.54mm through hole"
  rect 1.5x1.5 hole 0.9: 1(-11.43,-1.27)
  round 1.5 hole 0.9: 2(-11.43,1.27) 3(-8.89,-1.27) 4(-8.89,1.27) 5(-6.35,-1.27) 6(-6.35,1.27) 7(-3.81,-1.27) 8(-3.81,1.27) 9(-1.27,-1.27) 10(-1.27,1.27) 11(1.27,-1.27) 12(1.27,1.27) 13(3.81,-1.27) 14(3.81,1.27) 15(6.35,-1.27) 16(6.35,1.27) 17(8.89,-1.27) 18(8.89,1.27) 19(11.43,-1.27) 20(11.43,1.27)
  silkscreen extent -12.7,-2.54 12.7,2.54
INDC1005X04L [mm] "Chip Inductor, 2-Leads, Body 1.0x0.5mm, IPC High Density"
  rect 0.65x0.5 smd: 1(-0.475,0) 2(0.475,0)
  silkscreen extent -0.9,-0.35 0.9,0.35, body extent -0.5,-0.3 0.5,0.3, height 0.5
INDC1608X06L [mm] "Chip Inductor, 2-Leads, Body 1.6x0.8mm, IPC High Density"
  rect 0.75x0.8 smd: 1(-0.675,0) 2(0.675,0)
  silkscreen extent -1.17,-0.5 1.17,0.5, body extent -0.8,-0.48 0.8,0.48, height 0.8
LED_0603_G [mil] "SMD Super Bright LED, GREEN"
  rect 30x32 smd: 1(-27.5,0) 2(27.5,0)
  silkscreen extent -58,-20 48,20, body extent -32,-16 32,16, height 24
LED_DUAL_0606 [mm]
  rect 0.65x0.85 smd paste+0 mask+0.05: 1(0.425,0.725) 2(-0.425,0.725) 3(0.425,-0.725) 4(-0.425,-0.725)
  silkscreen extent -0.75,-0.8 0.75,0.8, body extent -0.75,-0.8 0.75,0.8, height 0.55
LIST_1x6_SMD-NC [mm] "Pin List, 2.54mm, SMD"
  rect 1.02x2.19 smd: 1(0,-1.465) 1(0,1.465) 2(2.54,-1.465) 2(2.54,1.465) 3(5.08,-1.465) 3(5.08,1.465) 4(7.62,-1.465) 4(7.62,1.465) 5(10.16,-1.465) 5(10.16,1.465) 6(12.7,-1.465) 6(12.7,1.465)
  silkscreen extent -1.27,-1.27 13.97,1.27
LIST_1x8_SMD [mm] "Pin List, 2.54mm, SMD"
  rect 1.02x2.19 smd: 1(0,-1.465) 1(0,1.465) 2(2.54,-1.465) 2(2.54,1.465) 3(5.08,-1.465) 3(5.08,1.465) 4(7.62,-1.465) 4(7.62,1.465) 5(10.16,-1.465) 5(10.16,1.465) 6(12.7,-1.465) 6(12.7,1.465) 7(15.24,-1.465) 7(15.24,1.465) 8(17.78,-1.465) 8(17.78,1.465)
  silkscreen extent -1.27,-1.27 19.05,1.27, body extent -1.27,-2.5 19.05,2.5, height 9.82
LIST_1x8_SMD-NC [mm] "Pin List, 2.54mm, SMD"
  rect 1.02x2.19 smd: 1(0,-1.465) 1(0,1.465) 2(2.54,-1.465) 2(2.54,1.465) 3(5.08,-1.465) 3(5.08,1.465) 4(7.62,-1.465) 4(7.62,1.465) 5(10.16,-1.465) 5(10.16,1.465) 6(12.7,-1.465) 6(12.7,1.465) 7(15.24,-1.465) 7(15.24,1.465) 8(17.78,-1.465) 8(17.78,1.465)
  silkscreen extent -1.27,-1.27 19.05,1.27
LIST_1x9_SMD-NC [mm] "Pin List, 2.54mm, SMD"
  rect 1.02x2.19 smd: 1(0,-1.465) 1(0,1.465) 2(2.54,-1.465) 2(2.54,1.465) 3(5.08,-1.465) 3(5.08,1.465) 4(7.62,-1.465) 4(7.62,1.465) 5(10.16,-1.465) 5(10.16,1.465) 6(12.7,-1.465) 6(12.7,1.465) 7(15.24,-1.465) 7(15.24,1.465) 8(17.78,-1.465) 8(17.78,1.465) 9(20.32,-1.465) 9(20.32,1.465)
  silkscreen extent -1.27,-1.27 21.59,1.27
LIST_1x10_SMD-NC [mm] "Pin List, 2.54mm, SMD"
  rect 1.02x2.19 smd: 1(0,-1.465) 1(0,1.465) 2(2.54,-1.465) 2(2.54,1.465) 3(5.08,-1.465) 3(5.08,1.465) 4(7.62,-1.465) 4(7.62,1.465) 5(10.16,-1.465) 5(10.16,1.465) 6(12.7,-1.465) 6(12.7,1.465) 7(15.24,-1.465) 7(15.24,1.465) 8(17.78,-1.465) 8(17.78,1.465) 9(20.32,-1.465) 9(20.32,1.465) 10(22.86,-1.465) 10(22.86,1.465)
  silkscreen extent -1.27,-1.27 24.13,1.27
LIST_ANG_1x2-SMD-2.54MM [mm] "Pin List, 2.54mm, Surface Mount, Angled"
  round 1.78 hole 1.78 unplated: 0(0,-4.496)
  rect 1.27x3.18 smd: 1(-1.27,0) 2(1.27,0)
  silkscreen extent -2.54,-11.58 2.54,-1.8, body extent -2.56,-11.61 2.52,1.35, height 3.03
QFN40P600X600X90-48N [mm] "QFN, 48-Leads, Body 6,0x6,0mm (max), Pitch 0,40mm, IPC Medium Density"
  oval 0.65x0.2 smd mask+0.05: 1(-3.025,2.2) 2(-3.025,1.8) 3(-3.025,1.4) 4(-3.025,1) 5(-3.025,0.6) 6(-3.025,0.2) 7(-3.025,-0.2) 8(-3.025,-0.6) 9(-3.025,-1) 10(-3.025,-1.4) 11(-3.025,-1.8) 12(-3.025,-2.2) 25(3.025,-2.2) 26(3.025,-1.8) 27(3.025,-1.4) 28(3.025,-1) 29(3.025,-0.6) 30(3.025,-0.2) 31(3.025,0.2) 32(3.025,0.6) 33(3.025,1) 34(3.025,1.4) 35(3.025,1.8) 36(3.025,2.2)
  oval 0.2x0.65 smd mask+0.05: 13(-2.2,-3.025) 14(-1.8,-3.025) 15(-1.4,-3.025) 16(-1,-3.025) 17(-0.6,-3.025) 18(-0.2,-3.025) 19(0.2,-3.025) 20(0.6,-3.025) 21(1,-3.025) 22(1.4,-3.025) 23(1.8,-3.025) 24(2.2,-3.025) 37(2.2,3.025) 38(1.8,3.025) 39(1.4,3.025) 40(1,3.025) 41(0.6,3.025) 42(0.2,3.025) 43(-0.2,3.025) 44(-0.6,3.025) 45(-1,3.025) 46(-1.4,3.025) 47(-1.8,3.025) 48(-2.2,3.025)
  rect 4.7x4.7 smd: 49(0,0)
  silkscreen extent -4.02,-3 3,3, body extent -3.02,-3.02 3.02,3.02, height 0.86
RESC0603X03L_C [mm] "Chip Resistor, 2-Leads, Body 0.6x0.3mm, IPC High Density"
  rect 0.27x0.3 smd: 1(-0.285,0) 2(0.285,0)
  silkscreen extent -0.49,-0.22 0.49,0.22, body extent -0.3,-0.15 0.3,0.15, height 0.23
RESC1005X04L [mm] "Chip Resistor, 2-Leads, Body 1.0x0.5mm, IPC High Density"
  rect 0.6x0.55 smd: 1(-0.5,0) 2(0.5,0)
  silkscreen extent -0.87,-0.38 0.88,0.38, body extent -0.5,-0.25 0.5,0.25, height 0.3
SOCKET_1x6_SMD [mm] "Socket, 2.54mm, SMD"
  rect 1.02x2.19 smd: 1(0,-1.465) 1(0,1.465) 2(2.54,-1.465) 2(2.54,1.465) 3(5.08,-1.465) 3(5.08,1.465) 4(7.62,-1.465) 4(7.62,1.465) 5(10.16,-1.465) 5(10.16,1.465) 6(12.7,1.465) 6(12.7,-1.465)
  silkscreen extent -1.27,-1.27 13.97,1.27, body extent -1.27,-2.29 13.97,2.29, height 7.47
SOCKET_1x8_SMD [mm] "Socket, 2.54mm, SMD"
  rect 1.02x2.19 smd: 1(0,-1.465) 1(0,1.465) 2(2.54,-1.465) 2(2.54,1.465) 3(5.08,-1.465) 3(5.08,1.465) 4(7.62,-1.465) 4(7.62,1.465) 5(10.16,-1.465) 5(10.16,1.465) 6(12.7,1.465) 6(12.7,-1.465) 7(15.24,-1.465) 7(15.24,1.465) 8(17.78,-1.465) 8(17.78,1.465)
  silkscreen extent -1.27,-1.27 19.05,1.27, body extent -1.27,-2.29 19.05,2.29, height 7.47
SOCKET_1x9_SMD [mm] "Socket, 2.54mm, SMD"
  rect 1.02x2.19 smd: 1(0,1.465) 1(0,-1.465) 2(2.54,-1.465) 2(2.54,1.465) 3(5.08,-1.465) 3(5.08,1.465) 4(7.62,-1.465) 4(7.62,1.465) 5(10.16,-1.465) 5(10.16,1.465) 6(12.7,1.465) 6(12.7,-1.465) 7(15.24,-1.465) 7(15.24,1.465) 8(17.78,-1.465) 8(17.78,1.465) 9(20.32,-1.465) 9(20.32,1.465)
  silkscreen extent -1.27,-1.27 21.59,1.27, body extent -1.26,-2.3 21.6,2.28, height 7.47
SOCKET_1x10_SMD [mm] "Socket, 2.54mm, SMD"
  rect 1.02x2.19 smd: 1(0,1.465) 1(0,-1.465) 2(2.54,-1.465) 2(2.54,1.465) 3(5.08,-1.465) 3(5.08,1.465) 4(7.62,-1.465) 4(7.62,1.465) 5(10.16,-1.465) 5(10.16,1.465) 6(12.7,-1.465) 6(12.7,1.465) 7(15.24,-1.465) 7(15.24,1.465) 8(17.78,-1.465) 8(17.78,1.465) 9(20.32,-1.465) 9(20.32,1.465) 10(22.86,-1.465) 10(22.86,1.465)
  silkscreen extent -1.27,-1.27 24.13,1.27, body extent -1.27,-2.29 24.13,2.29, height 7.47
SOCKET_2x3_SMD-2.54mm-bottom-NC [mm] "Socket, 2.54mm, SMD"
  rect 1.02x2.22 smd far side: 1(-2.54,-2.825) 2(-2.54,2.825) 3(0,-2.825) 4(0,2.825) 5(2.54,-2.825) 6(2.54,2.825)
SOD-523 [mm]
  rect 0.4x0.5 smd: 1(0.7,0) 3(-0.7,0)
  silkscreen extent -0.6,-0.4 0.6,0.4, body extent -0.8,-0.4 0.8,0.4, height 0.7
SODFL100X40-2N [mm] "SODFL, 2-Leads, Body 0.60x1.00mm, IPC Medium Density"
  rect 0.36x0.25 smd: 1(-0.42,0) 2(0.42,0)
  silkscreen extent -0.7,-0.35 0.5,0.5, body extent -0.5,-0.32 0.5,0.32, height 0.4
Solderbridge#1 [mm]
  round 0.2 smd paste-10: 1(-0.312,0) 2(0.312,0)
  Top Layer region: -0.077,-0.432 -0.152,-0.505 -0.271,-0.467 -0.335,-0.424 -0.409,-0.351 -0.462,-0.292 -0.521,-0.193 -0.549,-0.099 -0.544,0.122 -0.518,0.193 -0.434,0.33 -0.351,0.411 -0.259,0.469 -0.157,0.5 -0.107,0.483 -0.077,0.43
  Top Layer region: 0.077,0.432 0.152,0.505 0.271,0.467 0.335,0.424 0.409,0.351 0.462,0.292 0.521,0.193 0.549,0.099 0.544,-0.122 0.518,-0.193 0.434,-0.33 0.351,-0.411 0.259,-0.469 0.157,-0.5 0.107,-0.483 0.077,-0.43
  Top Layer lines w0.152: -0.153,0.431 ccw(c-0.042,0) -0.153,-0.431 ; 0.153,0.431 cw(c0.042,0) 0.153,-0.431
Solderbridge#2 [mm]
  round 0.2 smd paste-10: 1(-0.312,0) 2(0.312,0)
  Top Layer region: -0.077,-0.432 -0.152,-0.505 -0.271,-0.467 -0.335,-0.424 -0.409,-0.351 -0.462,-0.292 -0.521,-0.193 -0.549,-0.099 -0.544,0.122 -0.518,0.193 -0.434,0.33 -0.351,0.411 -0.259,0.469 -0.157,0.5 -0.107,0.483 -0.077,0.43
  Top Layer region: 0.077,0.432 0.152,0.505 0.271,0.467 0.335,0.424 0.409,0.351 0.462,0.292 0.521,0.193 0.549,0.099 0.544,-0.122 0.518,-0.193 0.434,-0.33 0.351,-0.411 0.259,-0.469 0.157,-0.5 0.107,-0.483 0.077,-0.43
  Top Layer lines w0.152: 0.153,0.431 cw(c0.042,0) 0.443,0.193 cw(c0.042,0) 0.487,0 cw(c0.042,0) 0.443,-0.193 cw(c0.042,0) 0.153,-0.431 ; -0.153,0.431 ccw(c-0.042,0) -0.47,0.122 ccw(c-0.042,0) -0.47,-0.122 ccw(c-0.042,0) -0.153,-0.431
Solderbridge#3 [mm]
  round 0.2 smd paste-10: 1(-0.312,0) 2(0.312,0)
  Top Layer region: 0.077,0.432 0.152,0.505 0.271,0.467 0.335,0.424 0.409,0.351 0.462,0.292 0.521,0.193 0.549,0.099 0.544,-0.122 0.518,-0.193 0.434,-0.33 0.351,-0.411 0.259,-0.469 0.157,-0.5 0.107,-0.483 0.077,-0.43
  Top Layer region: -0.077,-0.432 -0.152,-0.505 -0.271,-0.467 -0.335,-0.424 -0.409,-0.351 -0.462,-0.292 -0.521,-0.193 -0.549,-0.099 -0.544,0.122 -0.518,0.193 -0.434,0.33 -0.351,0.411 -0.259,0.469 -0.157,0.5 -0.107,0.483 -0.077,0.43
  Top Layer lines w0.152: 0.153,0.431 cw(c0.042,0) 0.487,0.01 cw(c0.042,0) 0.487,-0.01 cw(c0.042,0) 0.153,-0.431 ; -0.153,0.431 ccw(c-0.042,0) -0.47,0.122 ccw(c-0.042,0) -0.47,-0.122 ccw(c-0.042,0) -0.153,-0.431
Solderbridge#4 [mm]
  round 0.2 smd paste-10: 1(-0.312,0) 2(0.312,0)
  Top Layer region: -0.077,-0.432 -0.152,-0.505 -0.271,-0.467 -0.335,-0.424 -0.409,-0.351 -0.462,-0.292 -0.521,-0.193 -0.549,-0.099 -0.544,0.122 -0.518,0.193 -0.434,0.33 -0.351,0.411 -0.259,0.469 -0.157,0.5 -0.107,0.483 -0.077,0.43
  Top Layer region: 0.077,0.432 0.152,0.505 0.271,0.467 0.335,0.424 0.409,0.351 0.462,0.292 0.521,0.193 0.549,0.099 0.544,-0.122 0.518,-0.193 0.434,-0.33 0.351,-0.411 0.259,-0.469 0.157,-0.5 0.107,-0.483 0.077,-0.43
  Top Layer lines w0.152: 0.153,-0.431 ccw(c0.042,0) 0.153,0.431 ; -0.153,-0.431 cw(c-0.042,0) -0.287,0.371 cw(c-0.042,0) -0.153,0.431
Solderbridge#5 [mm]
  round 0.2 smd paste-10: 1(-0.312,0) 2(0.312,0)
  Top Layer region: -0.077,-0.432 -0.152,-0.505 -0.271,-0.467 -0.335,-0.424 -0.409,-0.351 -0.462,-0.292 -0.521,-0.193 -0.549,-0.099 -0.544,0.122 -0.518,0.193 -0.434,0.33 -0.351,0.411 -0.259,0.469 -0.157,0.5 -0.107,0.483 -0.077,0.43
  Top Layer region: 0.077,0.432 0.152,0.505 0.271,0.467 0.335,0.424 0.409,0.351 0.462,0.292 0.521,0.193 0.549,0.099 0.544,-0.122 0.518,-0.193 0.434,-0.33 0.351,-0.411 0.259,-0.469 0.157,-0.5 0.107,-0.483 0.077,-0.43
  Top Layer lines w0.152: 0.153,-0.431 ccw(c0.042,0) 0.487,0 ccw(c0.042,0) 0.153,0.431 ; -0.153,-0.431 cw(c-0.042,0) -0.312,-0.353 cw(c-0.042,0) -0.487,0 cw(c-0.042,0) -0.153,0.431
Solderbridge#6 [mm]
  round 0.2 smd paste-10: 1(-0.312,0) 2(0.312,0)
  Top Layer region: -0.077,-0.432 -0.152,-0.505 -0.271,-0.467 -0.335,-0.424 -0.409,-0.351 -0.462,-0.292 -0.521,-0.193 -0.549,-0.099 -0.544,0.122 -0.518,0.193 -0.434,0.33 -0.351,0.411 -0.259,0.469 -0.157,0.5 -0.107,0.483 -0.077,0.43
  Top Layer region: 0.077,0.432 0.152,0.505 0.271,0.467 0.335,0.424 0.409,0.351 0.462,0.292 0.521,0.193 0.549,0.099 0.544,-0.122 0.518,-0.193 0.434,-0.33 0.351,-0.411 0.259,-0.469 0.157,-0.5 0.107,-0.483 0.077,-0.43
  Top Layer lines w0.152: 0.153,-0.431 ccw(c0.042,0) 0.153,0.431 ; -0.153,-0.431 cw(c-0.042,0) -0.487,0 cw(c-0.042,0) -0.312,0.353 cw(c-0.042,0) -0.153,0.431
Solderbridge_Shorted [mm]
  round 0.2 smd paste-10: 1(-0.338,0) 2(0.338,0)
  Top Layer region: 0.102,0.432 0.178,0.505 0.296,0.467 0.361,0.424 0.434,0.351 0.488,0.292 0.546,0.193 0.574,0.099 0.569,-0.122 0.544,-0.193 0.46,-0.33 0.376,-0.411 0.284,-0.469 0.183,-0.5 0.132,-0.483 0.102,-0.43
  Top Layer region: -0.102,-0.432 -0.178,-0.505 -0.296,-0.467 -0.361,-0.424 -0.434,-0.351 -0.488,-0.292 -0.546,-0.193 -0.574,-0.099 -0.569,0.122 -0.544,0.193 -0.46,0.33 -0.376,0.411 -0.284,0.469 -0.183,0.5 -0.132,0.483 -0.102,0.43
  Top Layer lines w0.152: -0.178,0.431 ccw(c-0.068,0) -0.178,-0.431 ; 0.178,0.431 cw(c0.068,0) 0.178,-0.431
  Top Layer lines w0.203: -0.338,0 0.338,0
Solderbridge_Shorted_Power [mm]
  round 0.2 smd paste-10: 1(-0.338,0) 2(0.338,0)
  Top Layer region: 0.102,0.432 0.178,0.505 0.296,0.467 0.361,0.424 0.434,0.351 0.488,0.292 0.546,0.193 0.574,0.099 0.569,-0.122 0.544,-0.193 0.46,-0.33 0.376,-0.411 0.284,-0.469 0.183,-0.5 0.132,-0.483 0.102,-0.43
  Top Layer region: -0.102,-0.432 -0.178,-0.505 -0.296,-0.467 -0.361,-0.424 -0.434,-0.351 -0.488,-0.292 -0.546,-0.193 -0.574,-0.099 -0.569,0.122 -0.544,0.193 -0.46,0.33 -0.376,0.411 -0.284,0.469 -0.183,0.5 -0.132,0.483 -0.102,0.43
  Top Layer lines w0.152: -0.178,0.431 ccw(c-0.068,0) -0.178,-0.431 ; 0.178,0.431 cw(c0.068,0) 0.178,-0.431
  Top Layer lines w0.508: -0.338,0 0.338,0
SOT190P230X110-4L [mm] "SOT143, 4-Leads, Body 3.0x2.5mm (max), Pitch 1.90mm, IPC High Density"
  rect 0.85x1 smd: 1(-1.025,0.75)
  rect 0.85x0.6 smd: 2(-1.025,-0.95) 3(1.025,-0.95) 4(1.025,0.95)
  silkscreen extent -1.15,-1.5 0.7,1.93, body extent -1.21,-1.46 1.21,1.46, height 1
SOT-23A [mil] "SOT-23 footprint"
  rect 30x40 smd: 1(0,0) 2(74.8,0) 3(37.4,82.68)
  silkscreen extent -39,-4 94,79, body extent -20,-5 95,87, height 39
Switch-PB-6.2x6.3mm-SMD [mm] "6.2×6.5mm TACT Switch, without ground connector"
  rect 2.75x1.4 smd: 1(-3.375,2) 1(3.375,2) 2(-3.375,-2) 2(3.375,-2)
  silkscreen extent -3,-3 3,3, body extent -4,-3 4,3.3, height 3.1
Switch-Slide-DPDT-8.5x3.6mm [mm] "Slide Switches - DPDT, SMD, ON-ON"
  rect 1.2x2.5 smd: 1(-2.5,-2.75) 2(0,-2.75) 3(2.5,-2.75) 4(-2.5,2.75) 5(0,2.75) 6(2.5,2.75)
  silkscreen extent -4.5,-1.8 4.5,1.8, body extent -4.52,-3.75 4.52,3.75, height 5.5
TC2050-IDC-NLFP [mil]
  round 39 hole 39 unplated: 0(-150,0) 0(150,-40) 0(150,40)
  round 31 smd paste-196.85: 1(-100,-25) 2(-50,-25) 3(0,-25) 4(50,-25) 5(100,-25) 6(100,25) 7(50,25) 8(0,25) 9(-50,25) 10(-100,25)
  Top Layer pour cut-out: -100,25 -100,-25 100,-25 100,25
TESTPAD-TH [mm]
  round 1.5 hole 1: 1(0,0)
  silkscreen extent -1,-1 1,1
TP_SMD_Ø1.0mm [mm]
  round 1 smd paste-5: 1(0,0)
  silkscreen extent -0.76,-0.76 0.76,0.76
TSQFP50P1600X1600X160-100N [mm] "TSQFP, 100-Leads, Body 16,0x16,0mm (max), Pitch 0,50mm, IPC Medium Density"
  oval 1.65x0.3 smd mask+0.05: 1(-7.575,6) 2(-7.575,5.5) 3(-7.575,5) 4(-7.575,4.5) 5(-7.575,4) 6(-7.575,3.5) 7(-7.575,3) 8(-7.575,2.5) 9(-7.575,2) 10(-7.575,1.5) 11(-7.575,1) 12(-7.575,0.5) 13(-7.575,0) 14(-7.575,-0.5) 15(-7.575,-1) 16(-7.575,-1.5) 17(-7.575,-2) 18(-7.575,-2.5) 19(-7.575,-3) 20(-7.575,-3.5) 21(-7.575,-4) 22(-7.575,-4.5) 23(-7.575,-5) 24(-7.575,-5.5) 25(-7.575,-6) 51(7.575,-6) 52(7.575,-5.5) 53(7.575,-5) 54(7.575,-4.5) 55(7.575,-4) 56(7.575,-3.5) 57(7.575,-3) 58(7.575,-2.5) 59(7.575,-2) 60(7.575,-1.5) 61(7.575,-1) 62(7.575,-0.5) 63(7.575,0) 64(7.575,0.5) 65(7.575,1) 66(7.575,1.5) 67(7.575,2) 68(7.575,2.5) 69(7.575,3) 70(7.575,3.5) 71(7.575,4) 72(7.575,4.5) 73(7.575,5) 74(7.575,5.5) 75(7.575,6)
  oval 0.3x1.65 smd mask+0.05: 26(-6,-7.575) 27(-5.5,-7.575) 28(-5,-7.575) 29(-4.5,-7.575) 30(-4,-7.575) 31(-3.5,-7.575) 32(-3,-7.575) 33(-2.5,-7.575) 34(-2,-7.575) 35(-1.5,-7.575) 36(-1,-7.575) 37(-0.5,-7.575) 38(0,-7.575) 39(0.5,-7.575) 40(1,-7.575) 41(1.5,-7.575) 42(2,-7.575) 43(2.5,-7.575) 44(3,-7.575) 45(3.5,-7.575) 46(4,-7.575) 47(4.5,-7.575) 48(5,-7.575) 49(5.5,-7.575) 50(6,-7.575) 76(6,7.575) 77(5.5,7.575) 78(5,7.575) 79(4.5,7.575) 80(4,7.575) 81(3.5,7.575) 82(3,7.575) 83(2.5,7.575) 84(2,7.575) 85(1.5,7.575) 86(1,7.575) 87(0.5,7.575) 88(0,7.575) 89(-0.5,7.575) 90(-1,7.575) 91(-1.5,7.575) 92(-2,7.575) 93(-2.5,7.575) 94(-3,7.575) 95(-3.5,7.575) 96(-4,7.575) 97(-4.5,7.575) 98(-5,7.575) 99(-5.5,7.575) 100(-6,7.575)
  silkscreen extent -7.7,-6.35 6.35,6.82, body extent -8,-8 8,8, height 1.6
USB-Micro-B-RA-SMD-PiP [mm] "Micro USB B SMT"
  rect 1.35x0.4 smd: 1(0,1.3) 2(0,0.65) 3(0,0) 4(0,-0.65) 5(0,-1.3)
  oval 1.6x0.9 hole 0.5 slot 1.2 at 0 deg: 6(-2.675,-3.3) 6(-2.675,3.3)
  oval 2x1.5 on Top Paste: 6(-2.675,-3.3) 6(-2.675,3.3)
  rect 1.55x1.9 smd: 6(-2.675,-1.2) 6(-2.675,1.2)
  rect 1.4x1.6 smd: 6(-0.225,-3.2) 6(-0.225,3.2)
  silkscreen extent -4.75,-3.75 0.25,3.75, body extent -5.28,-4.1 0.15,4.1, height 2.72
XQFN40P180X260X50-16N [mm] "QFN, 16-Leads, Body 1.80x2.60mm, Pitch 0.40mm, IPC Medium Density"
  oval 0.65x0.22 smd paste-0.02 mask+0.04: 1(-0.825,0.6) 2(-0.825,0.2) 3(-0.825,-0.2) 4(-0.825,-0.6) 9(0.825,-0.6) 10(0.825,-0.2) 11(0.825,0.2) 12(0.825,0.6)
  oval 0.22x0.65 smd paste-0.02 mask+0.04: 5(-0.6,-1.225) 6(-0.2,-1.225) 7(0.2,-1.225) 8(0.6,-1.225) 13(0.6,1.225) 14(0.2,1.225) 15(-0.2,1.225) 16(-0.6,1.225)
  silkscreen extent -1.45,-1.4 1,1.4, body extent -0.91,-1.31 0.91,1.31, height 0.55
XTAL_3215 [mm] "XTAL SMD 3.2 x 1.5 mm"
  rect 1x1.8 smd: 1(-1.25,0) 2(1.25,0)
  silkscreen extent -0.6,-0.75 0.6,0.75, body extent -1.6,-0.75 1.6,0.75, height 0.81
